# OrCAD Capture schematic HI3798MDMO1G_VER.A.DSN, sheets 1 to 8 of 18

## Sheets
1 SHEET_18: size A3
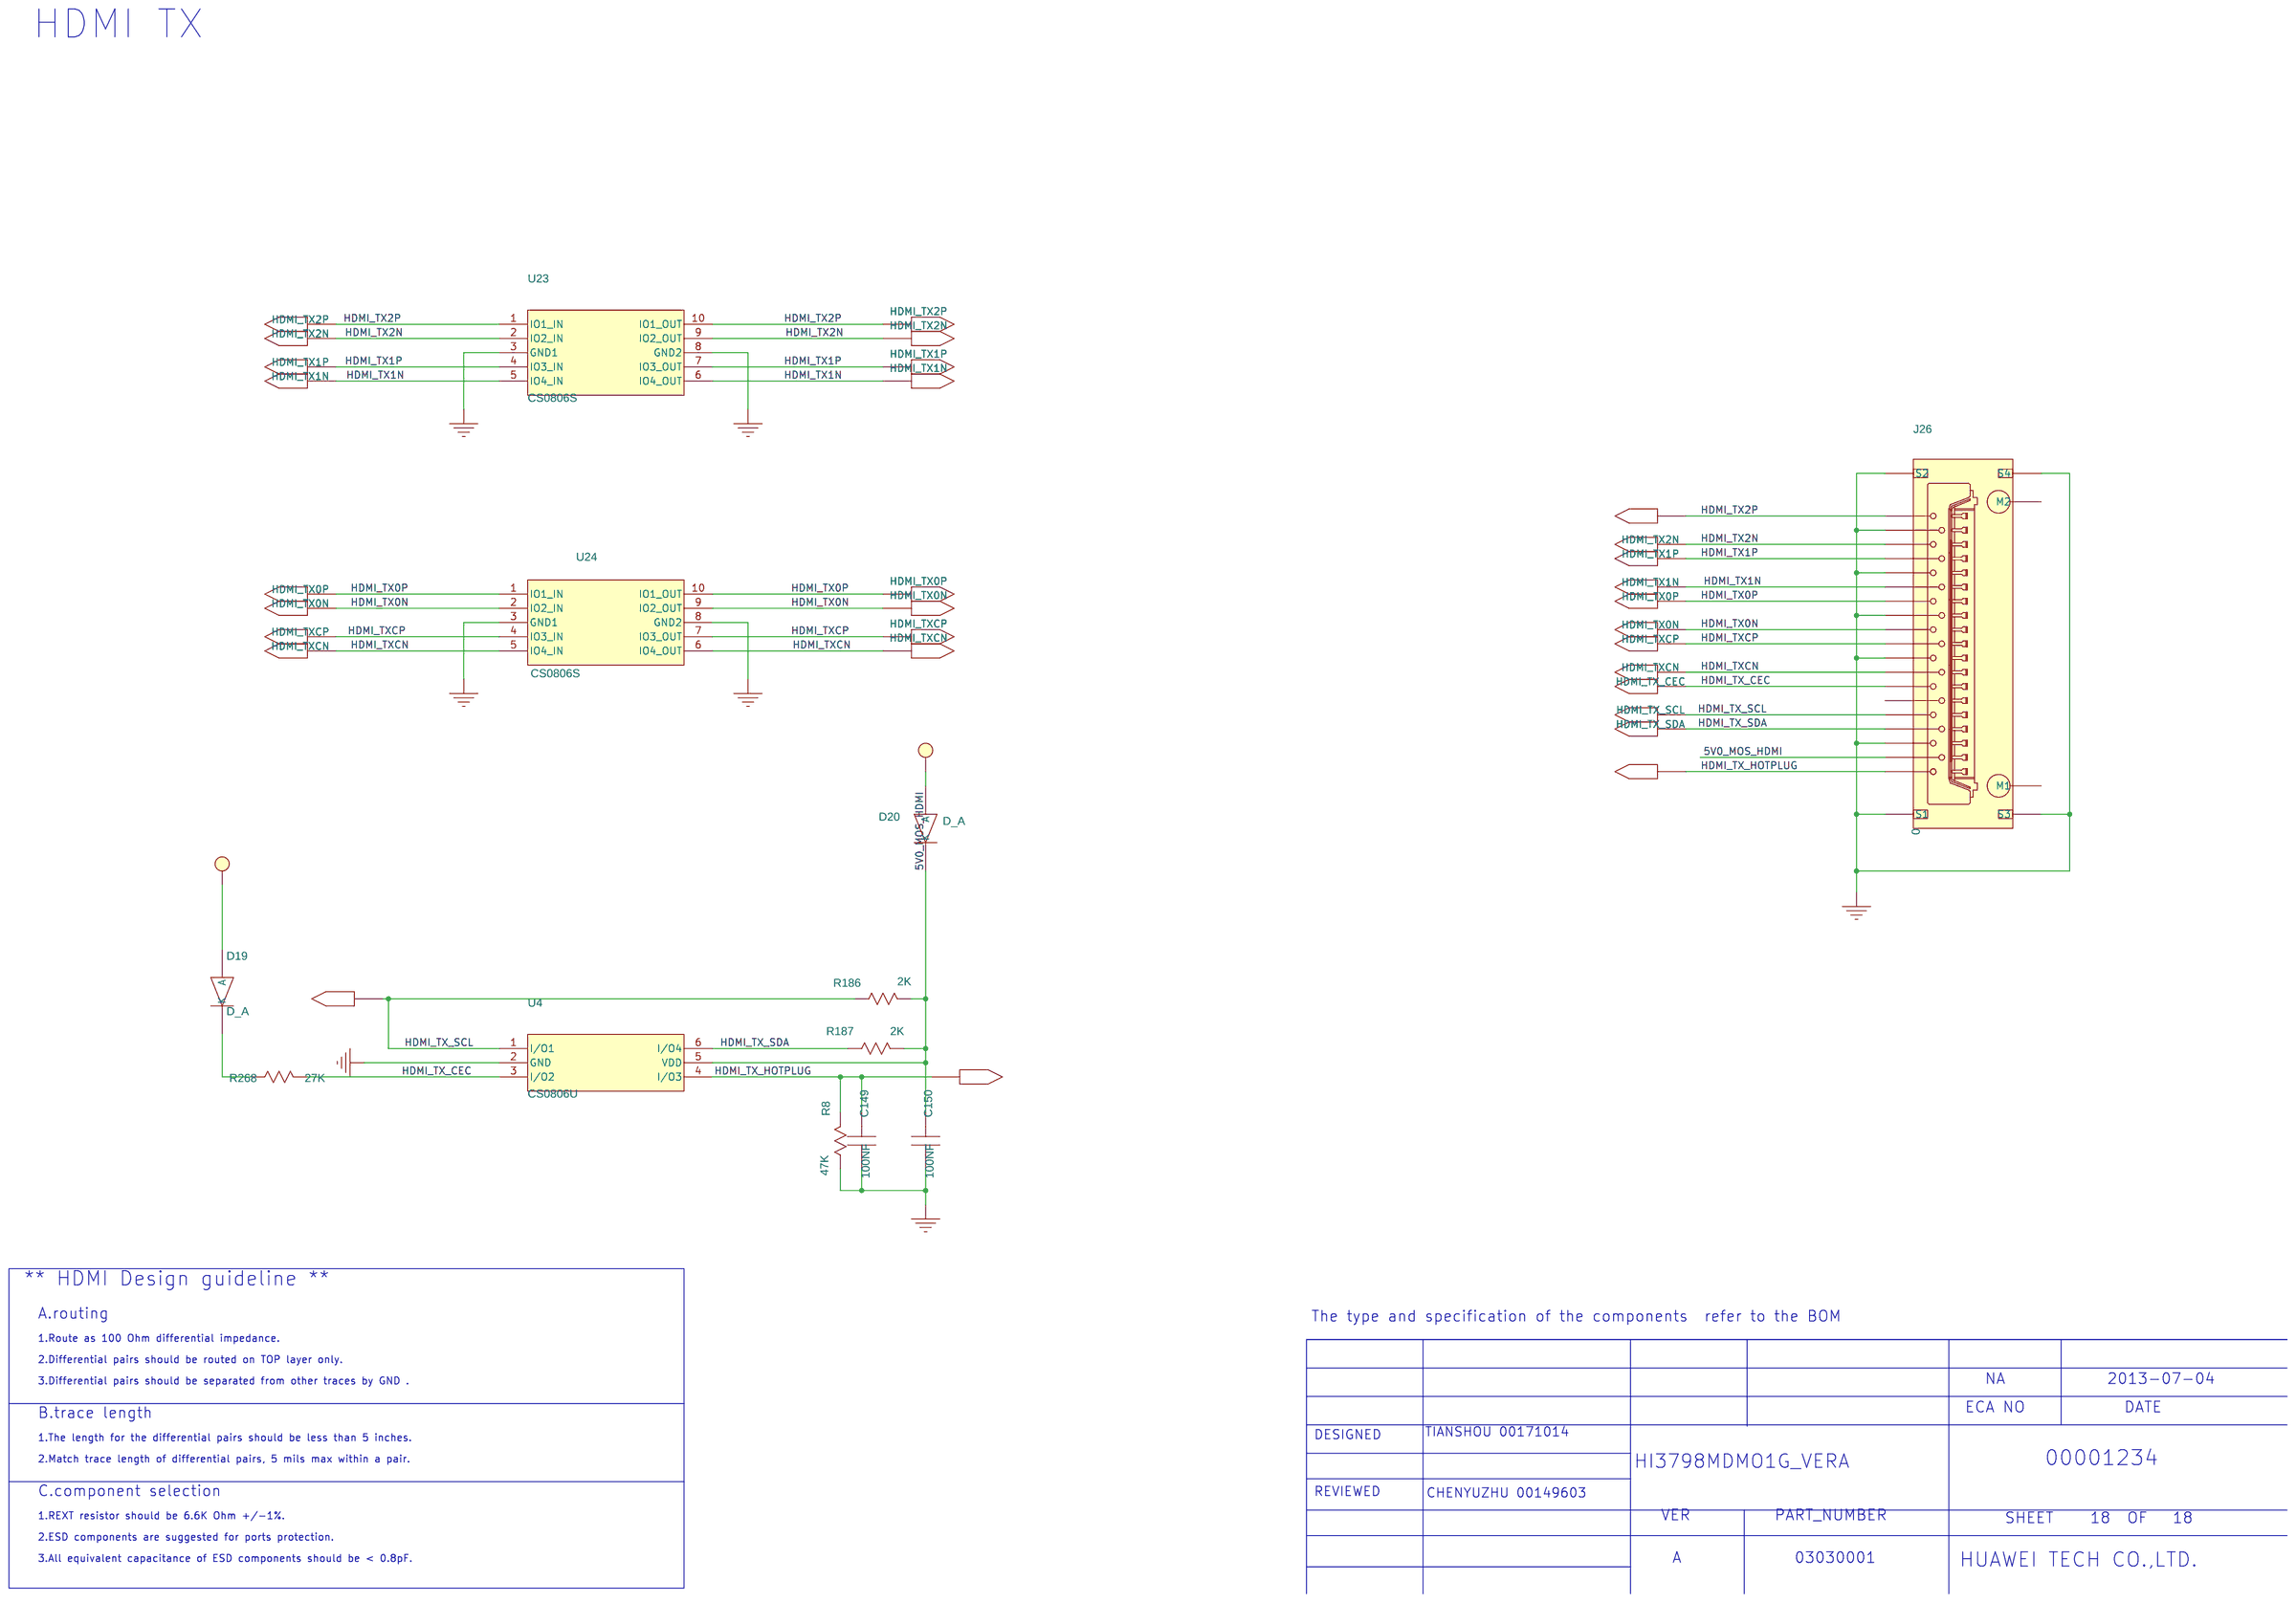
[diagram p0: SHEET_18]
2 SHEET_17: size A3
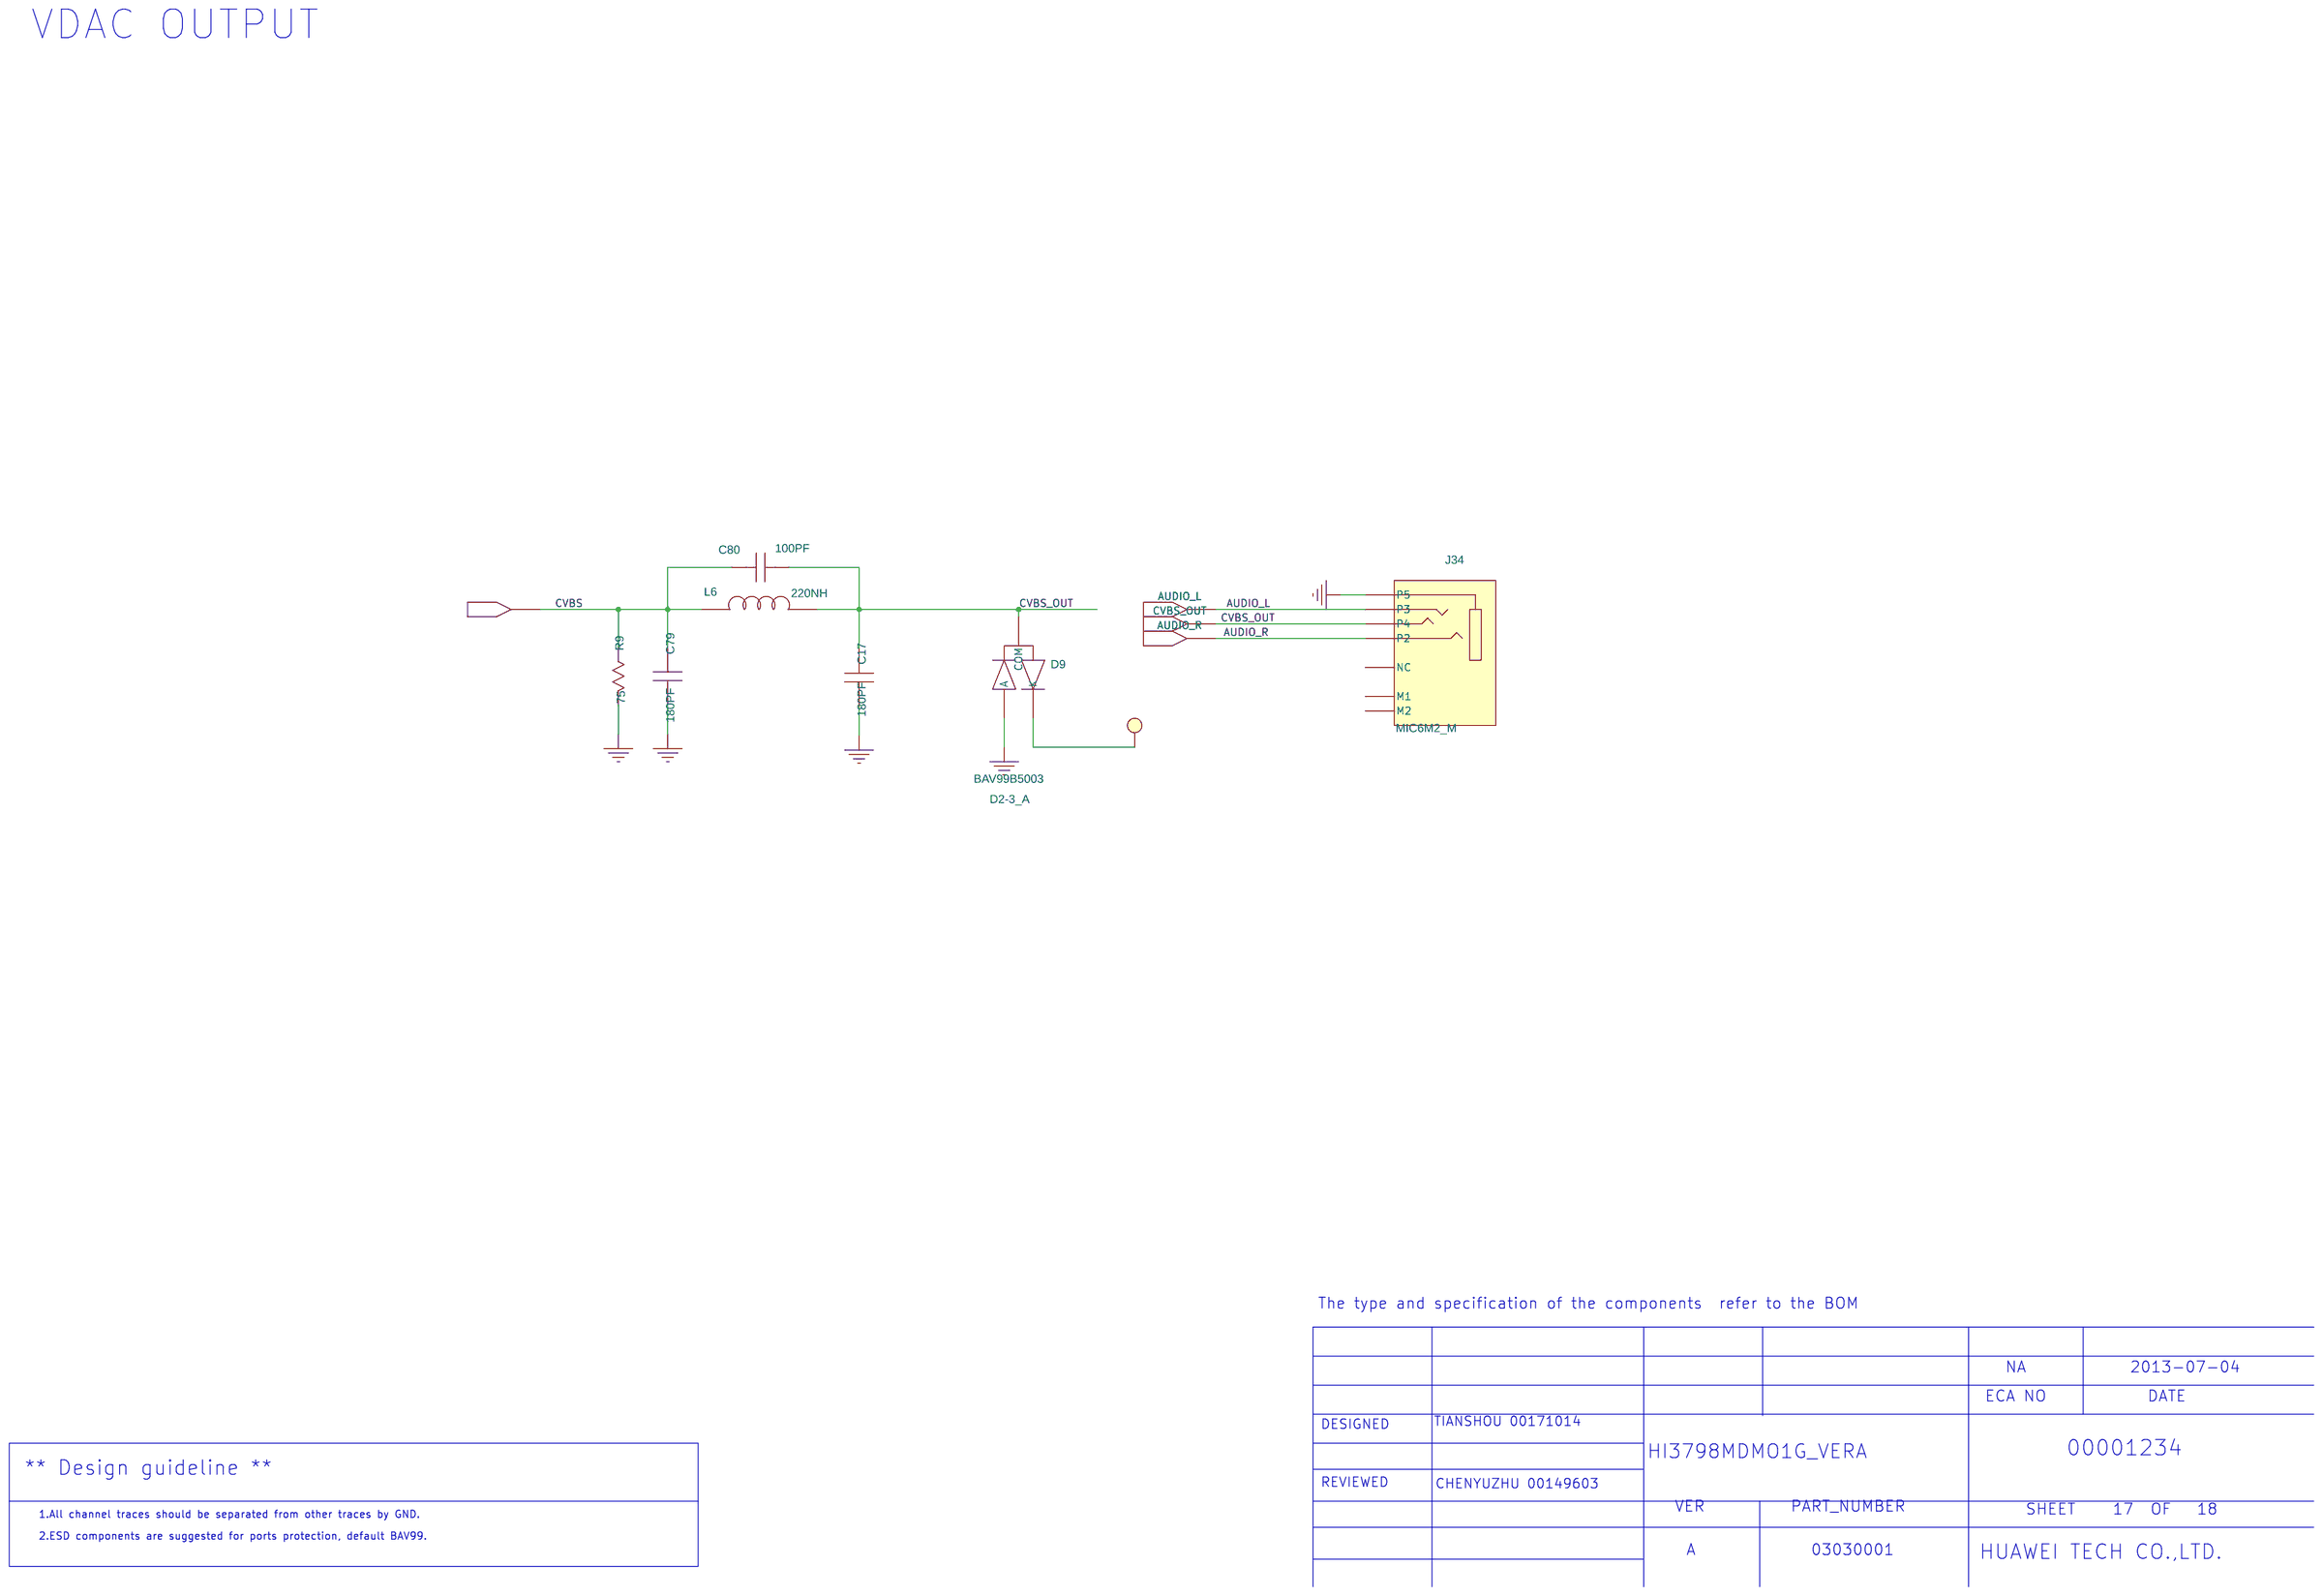
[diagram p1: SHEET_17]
3 SHEET_16: size A3
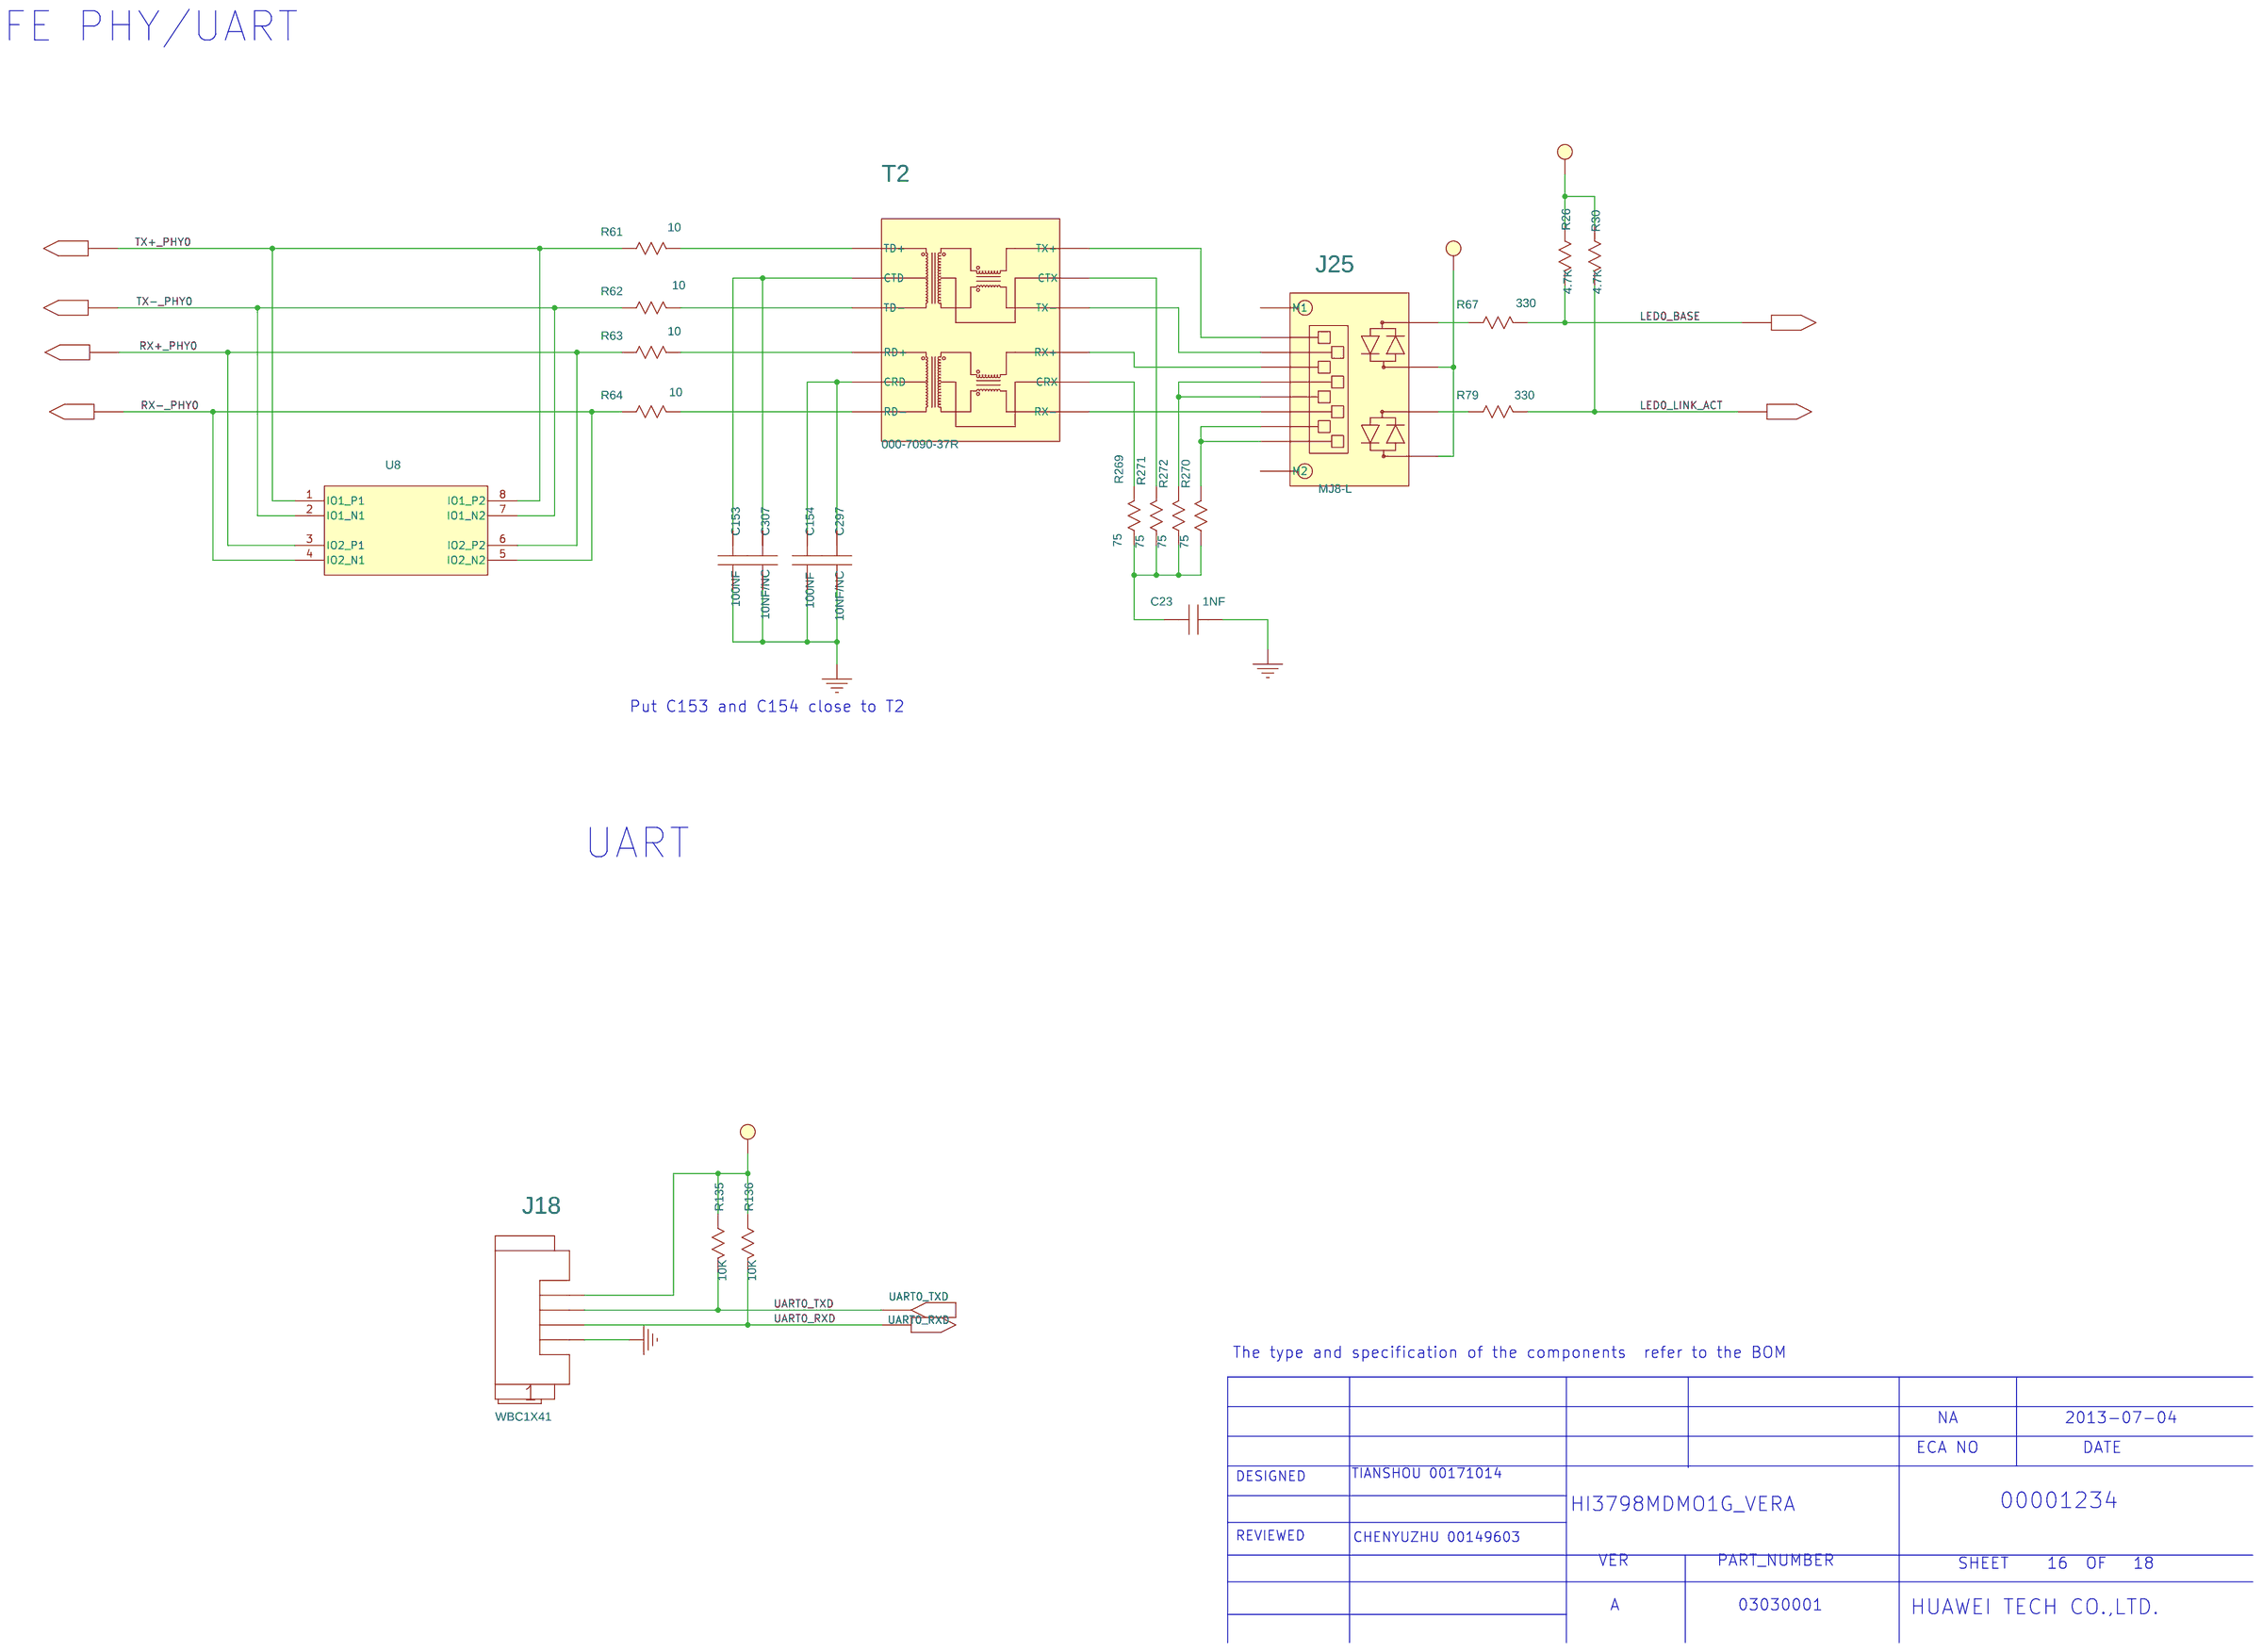
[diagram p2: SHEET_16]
4 SHEET_15: size A3
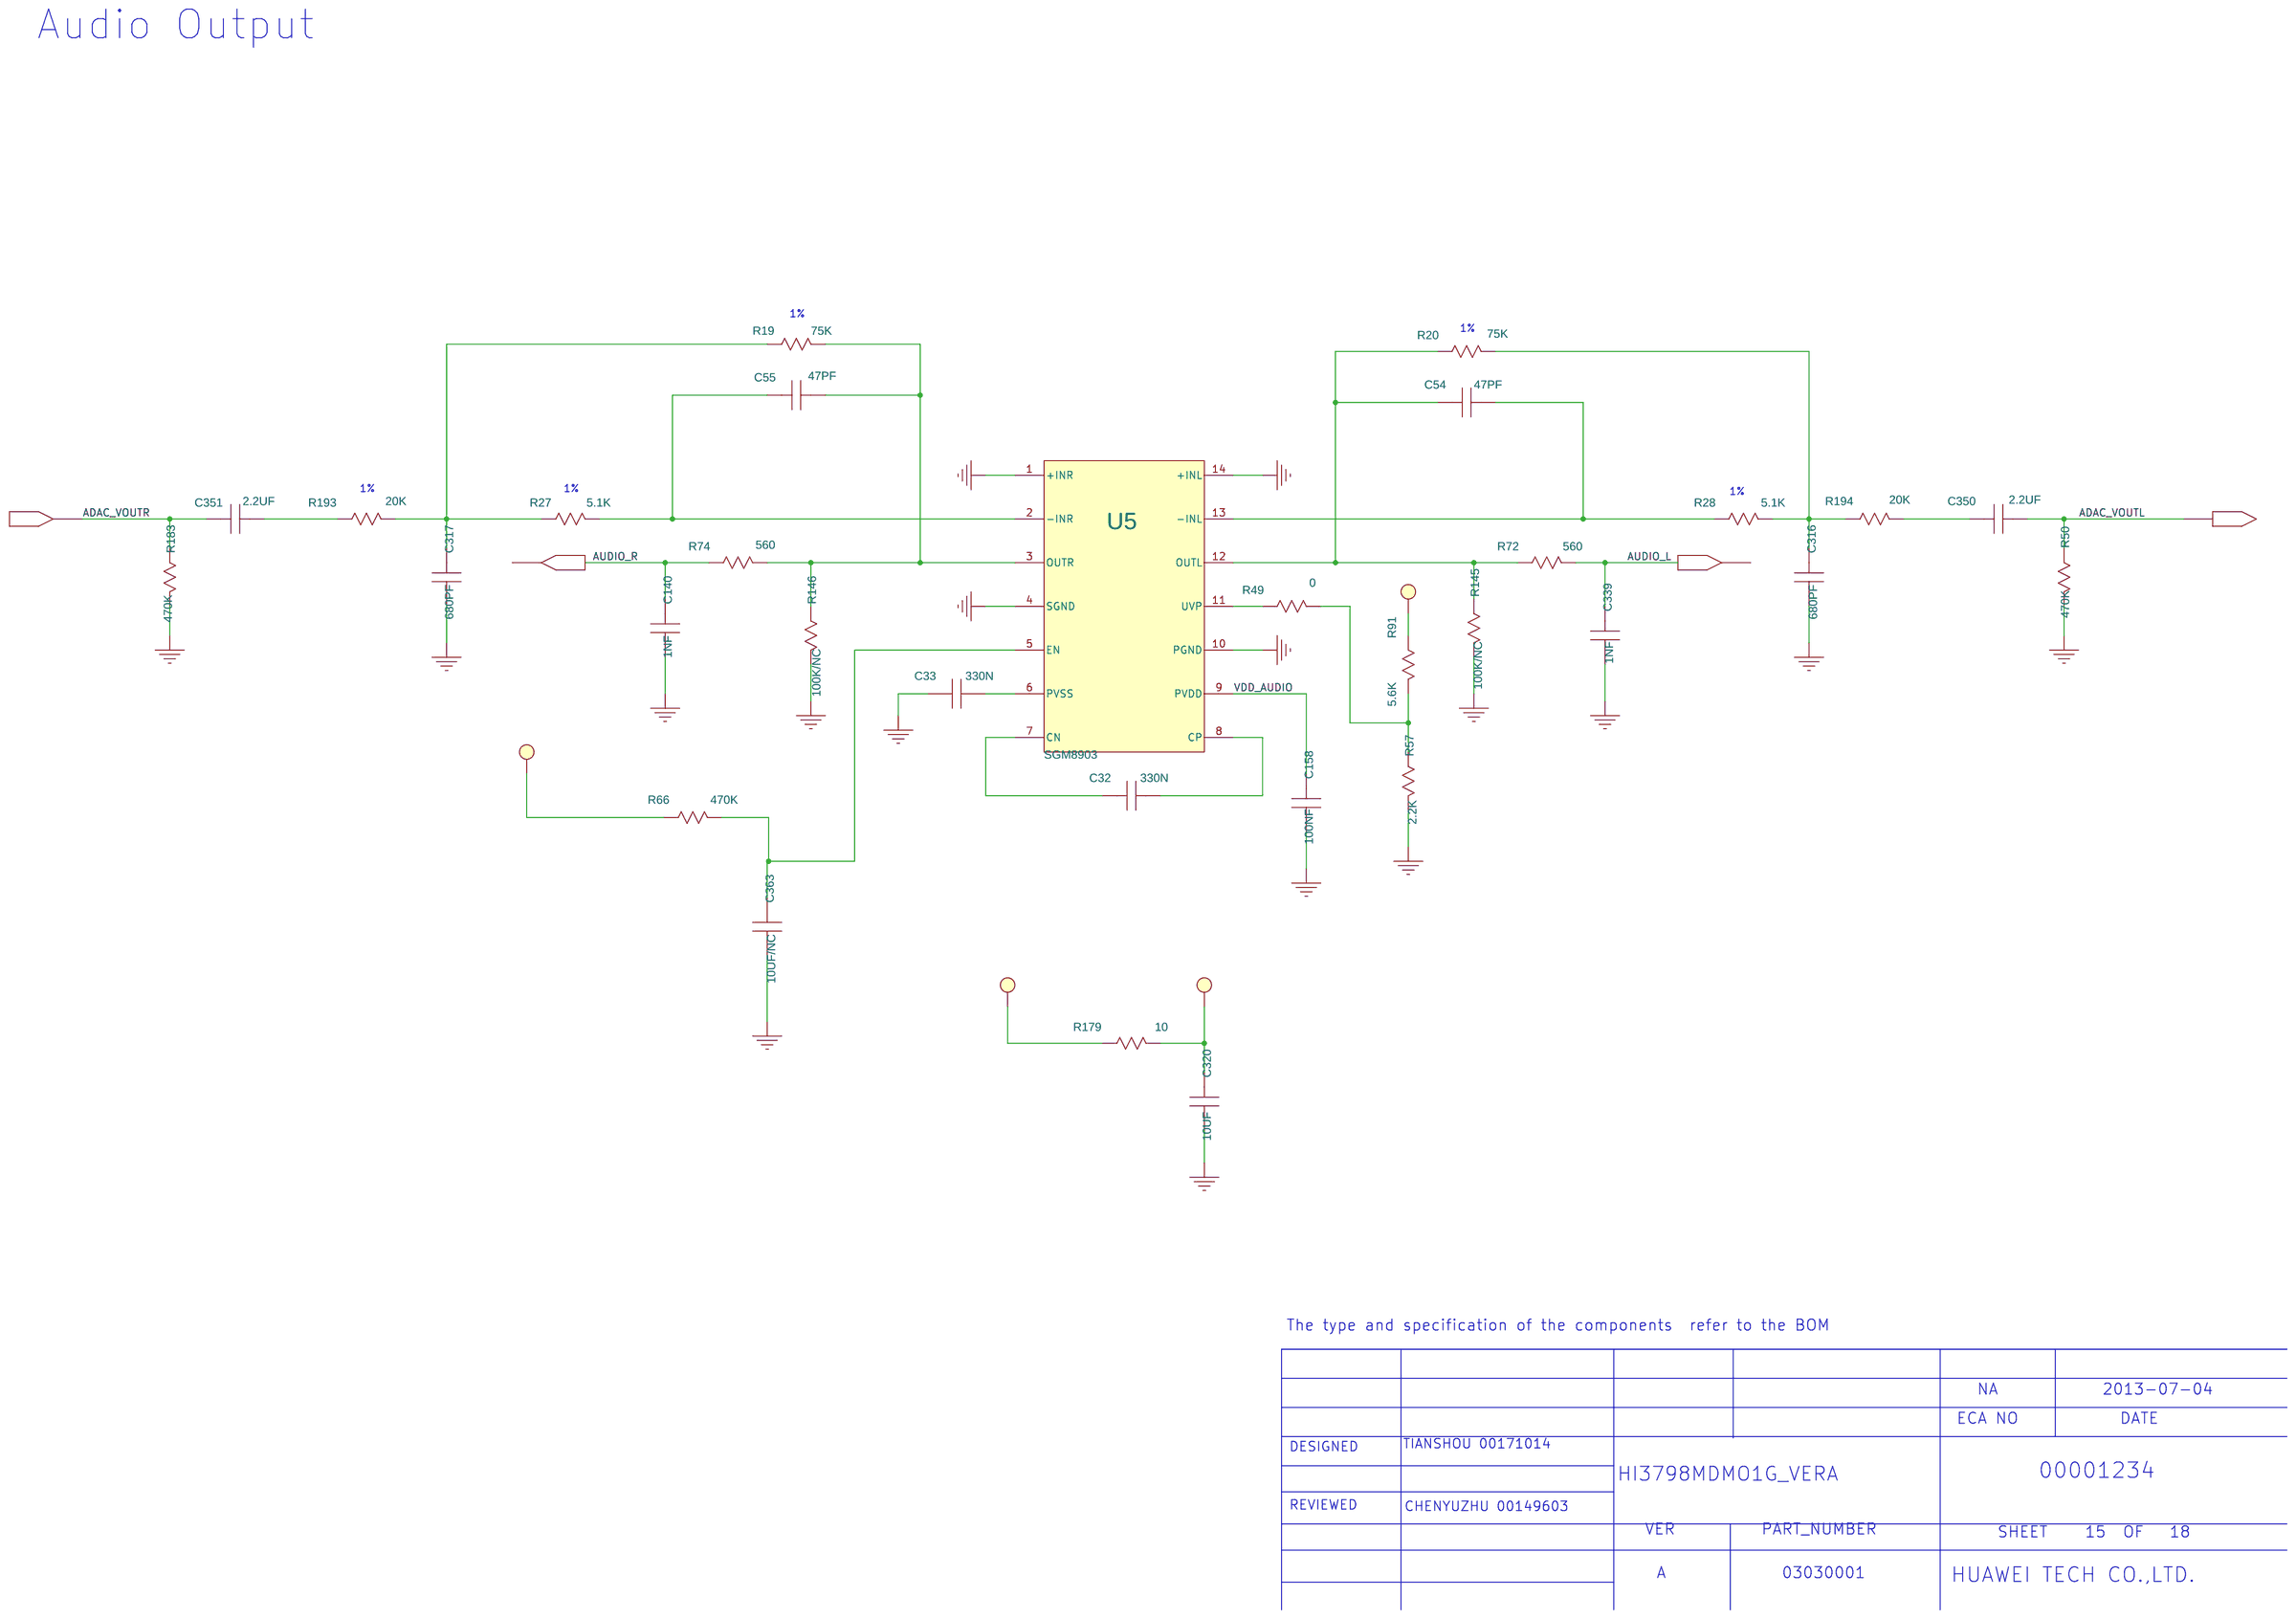
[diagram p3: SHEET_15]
5 SHEET_14: size A3
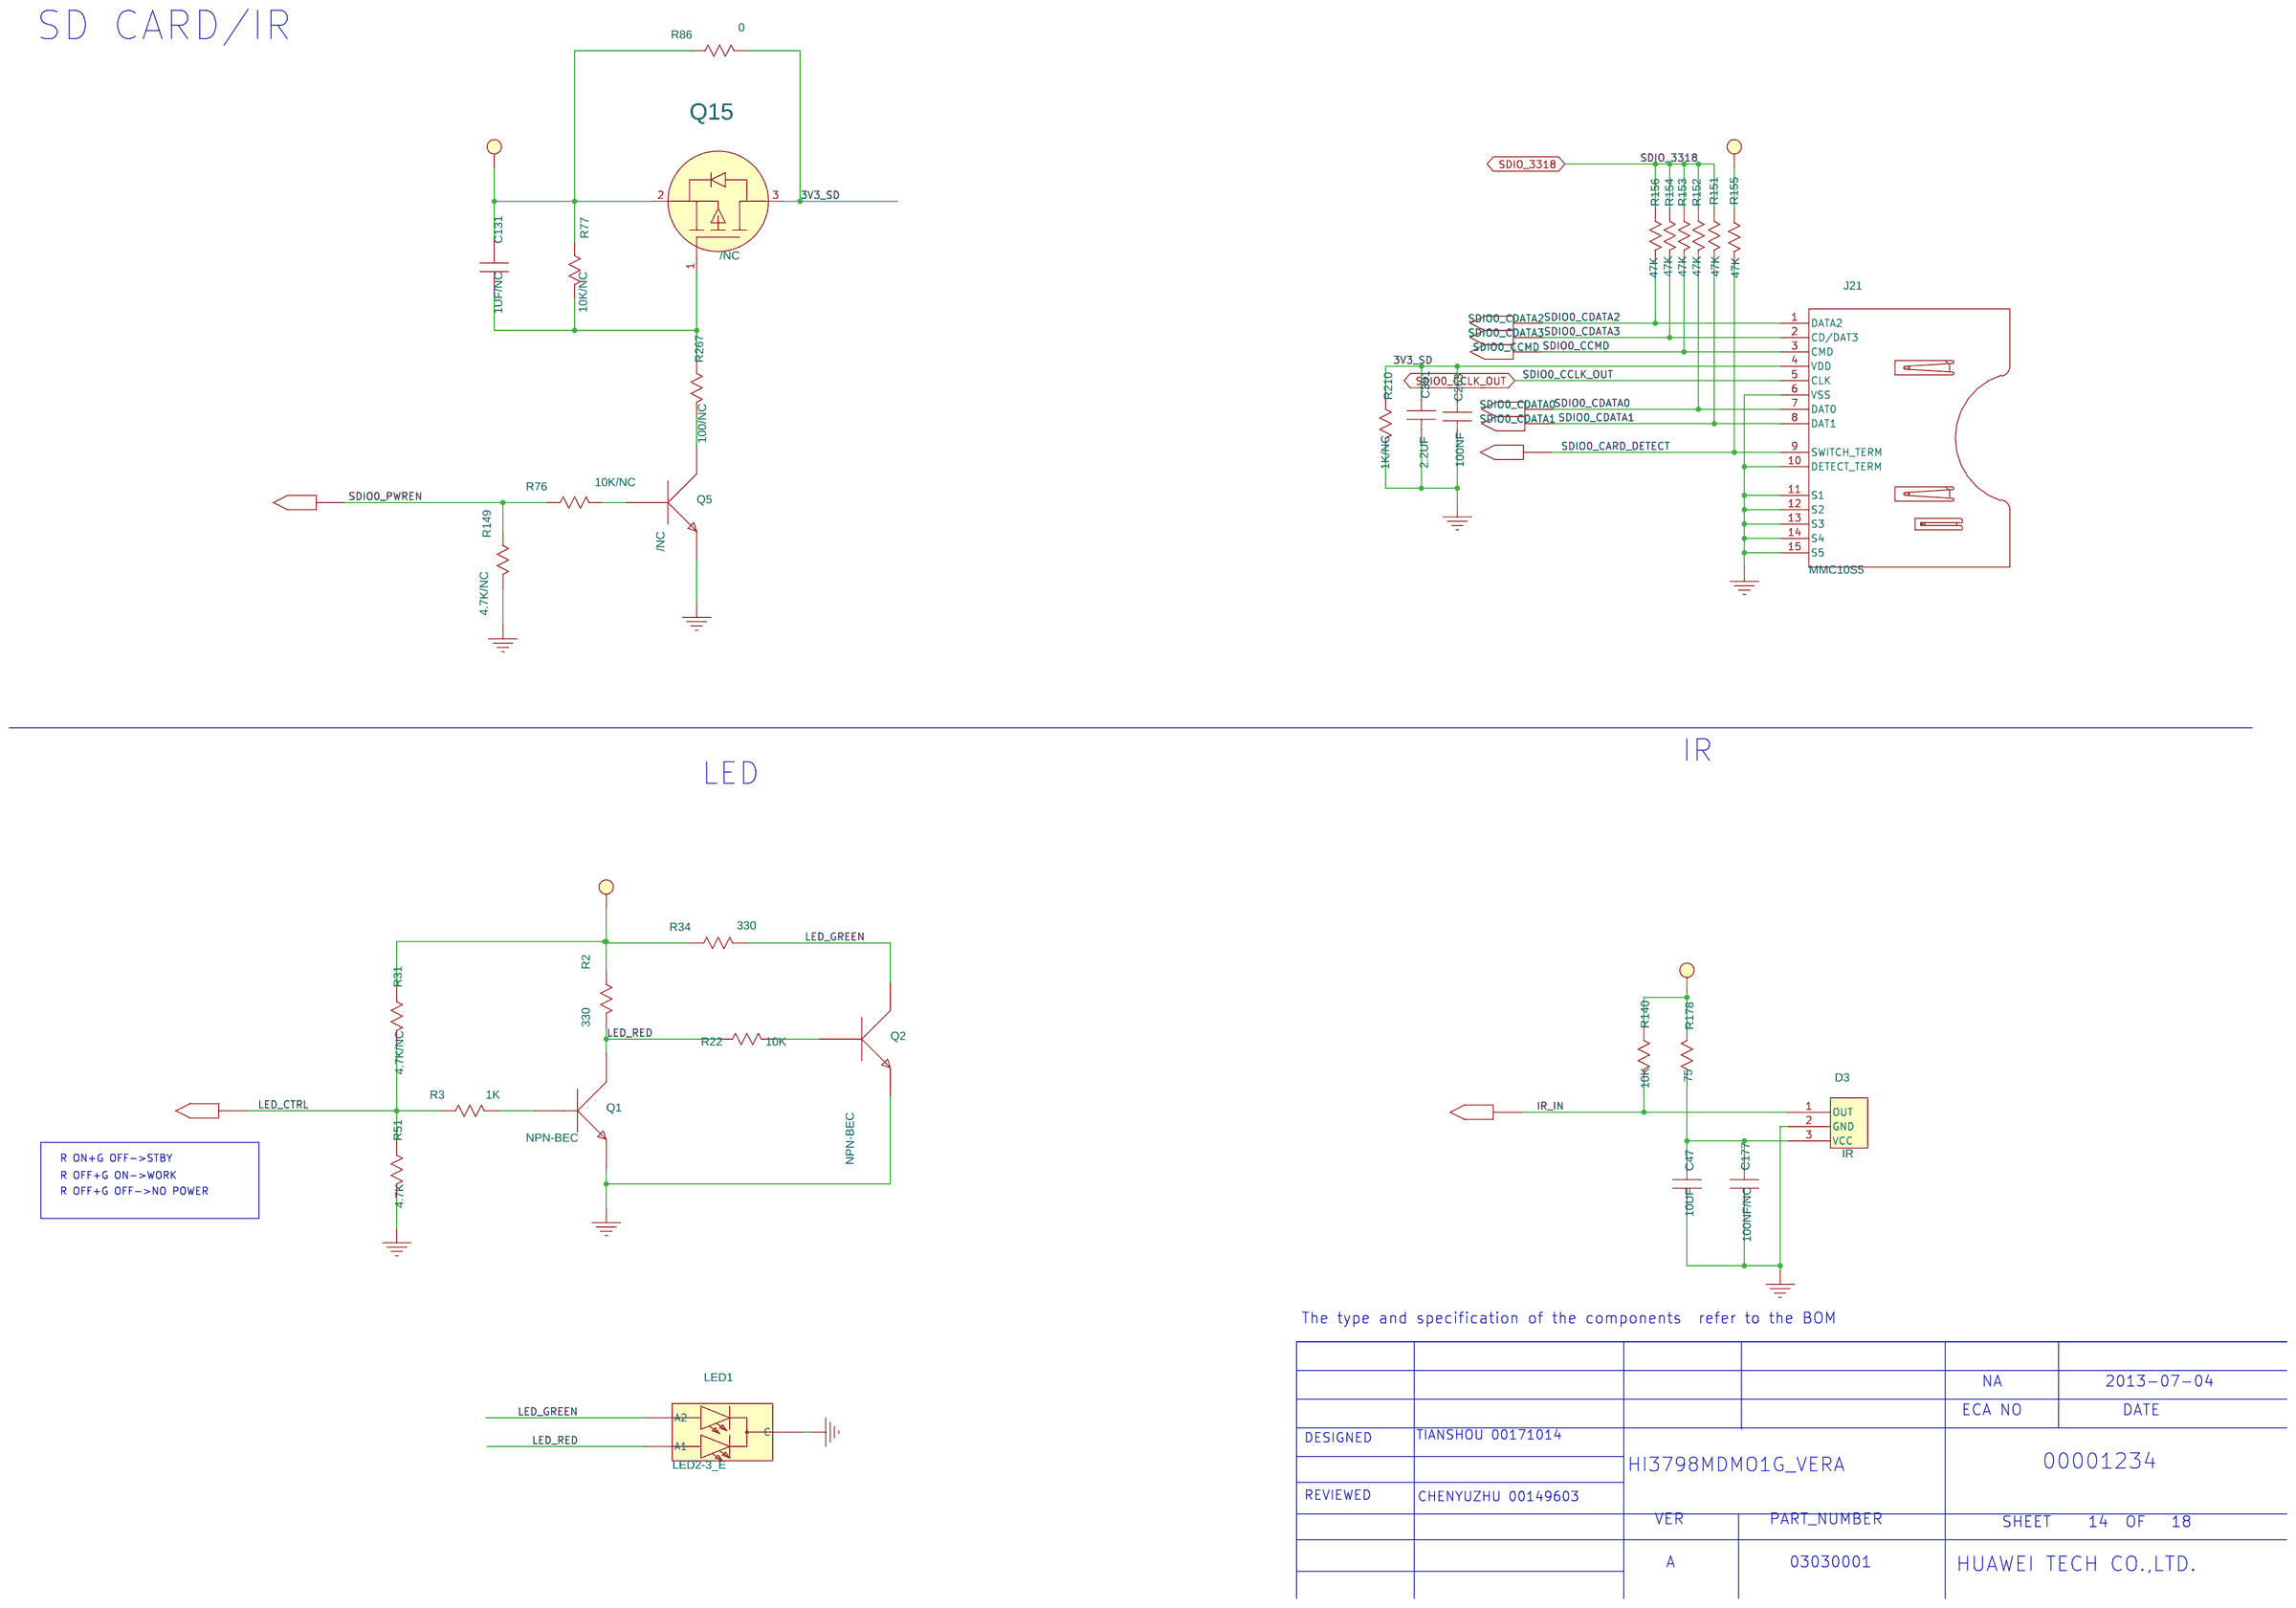
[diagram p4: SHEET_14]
6 SHEET_13: size A3
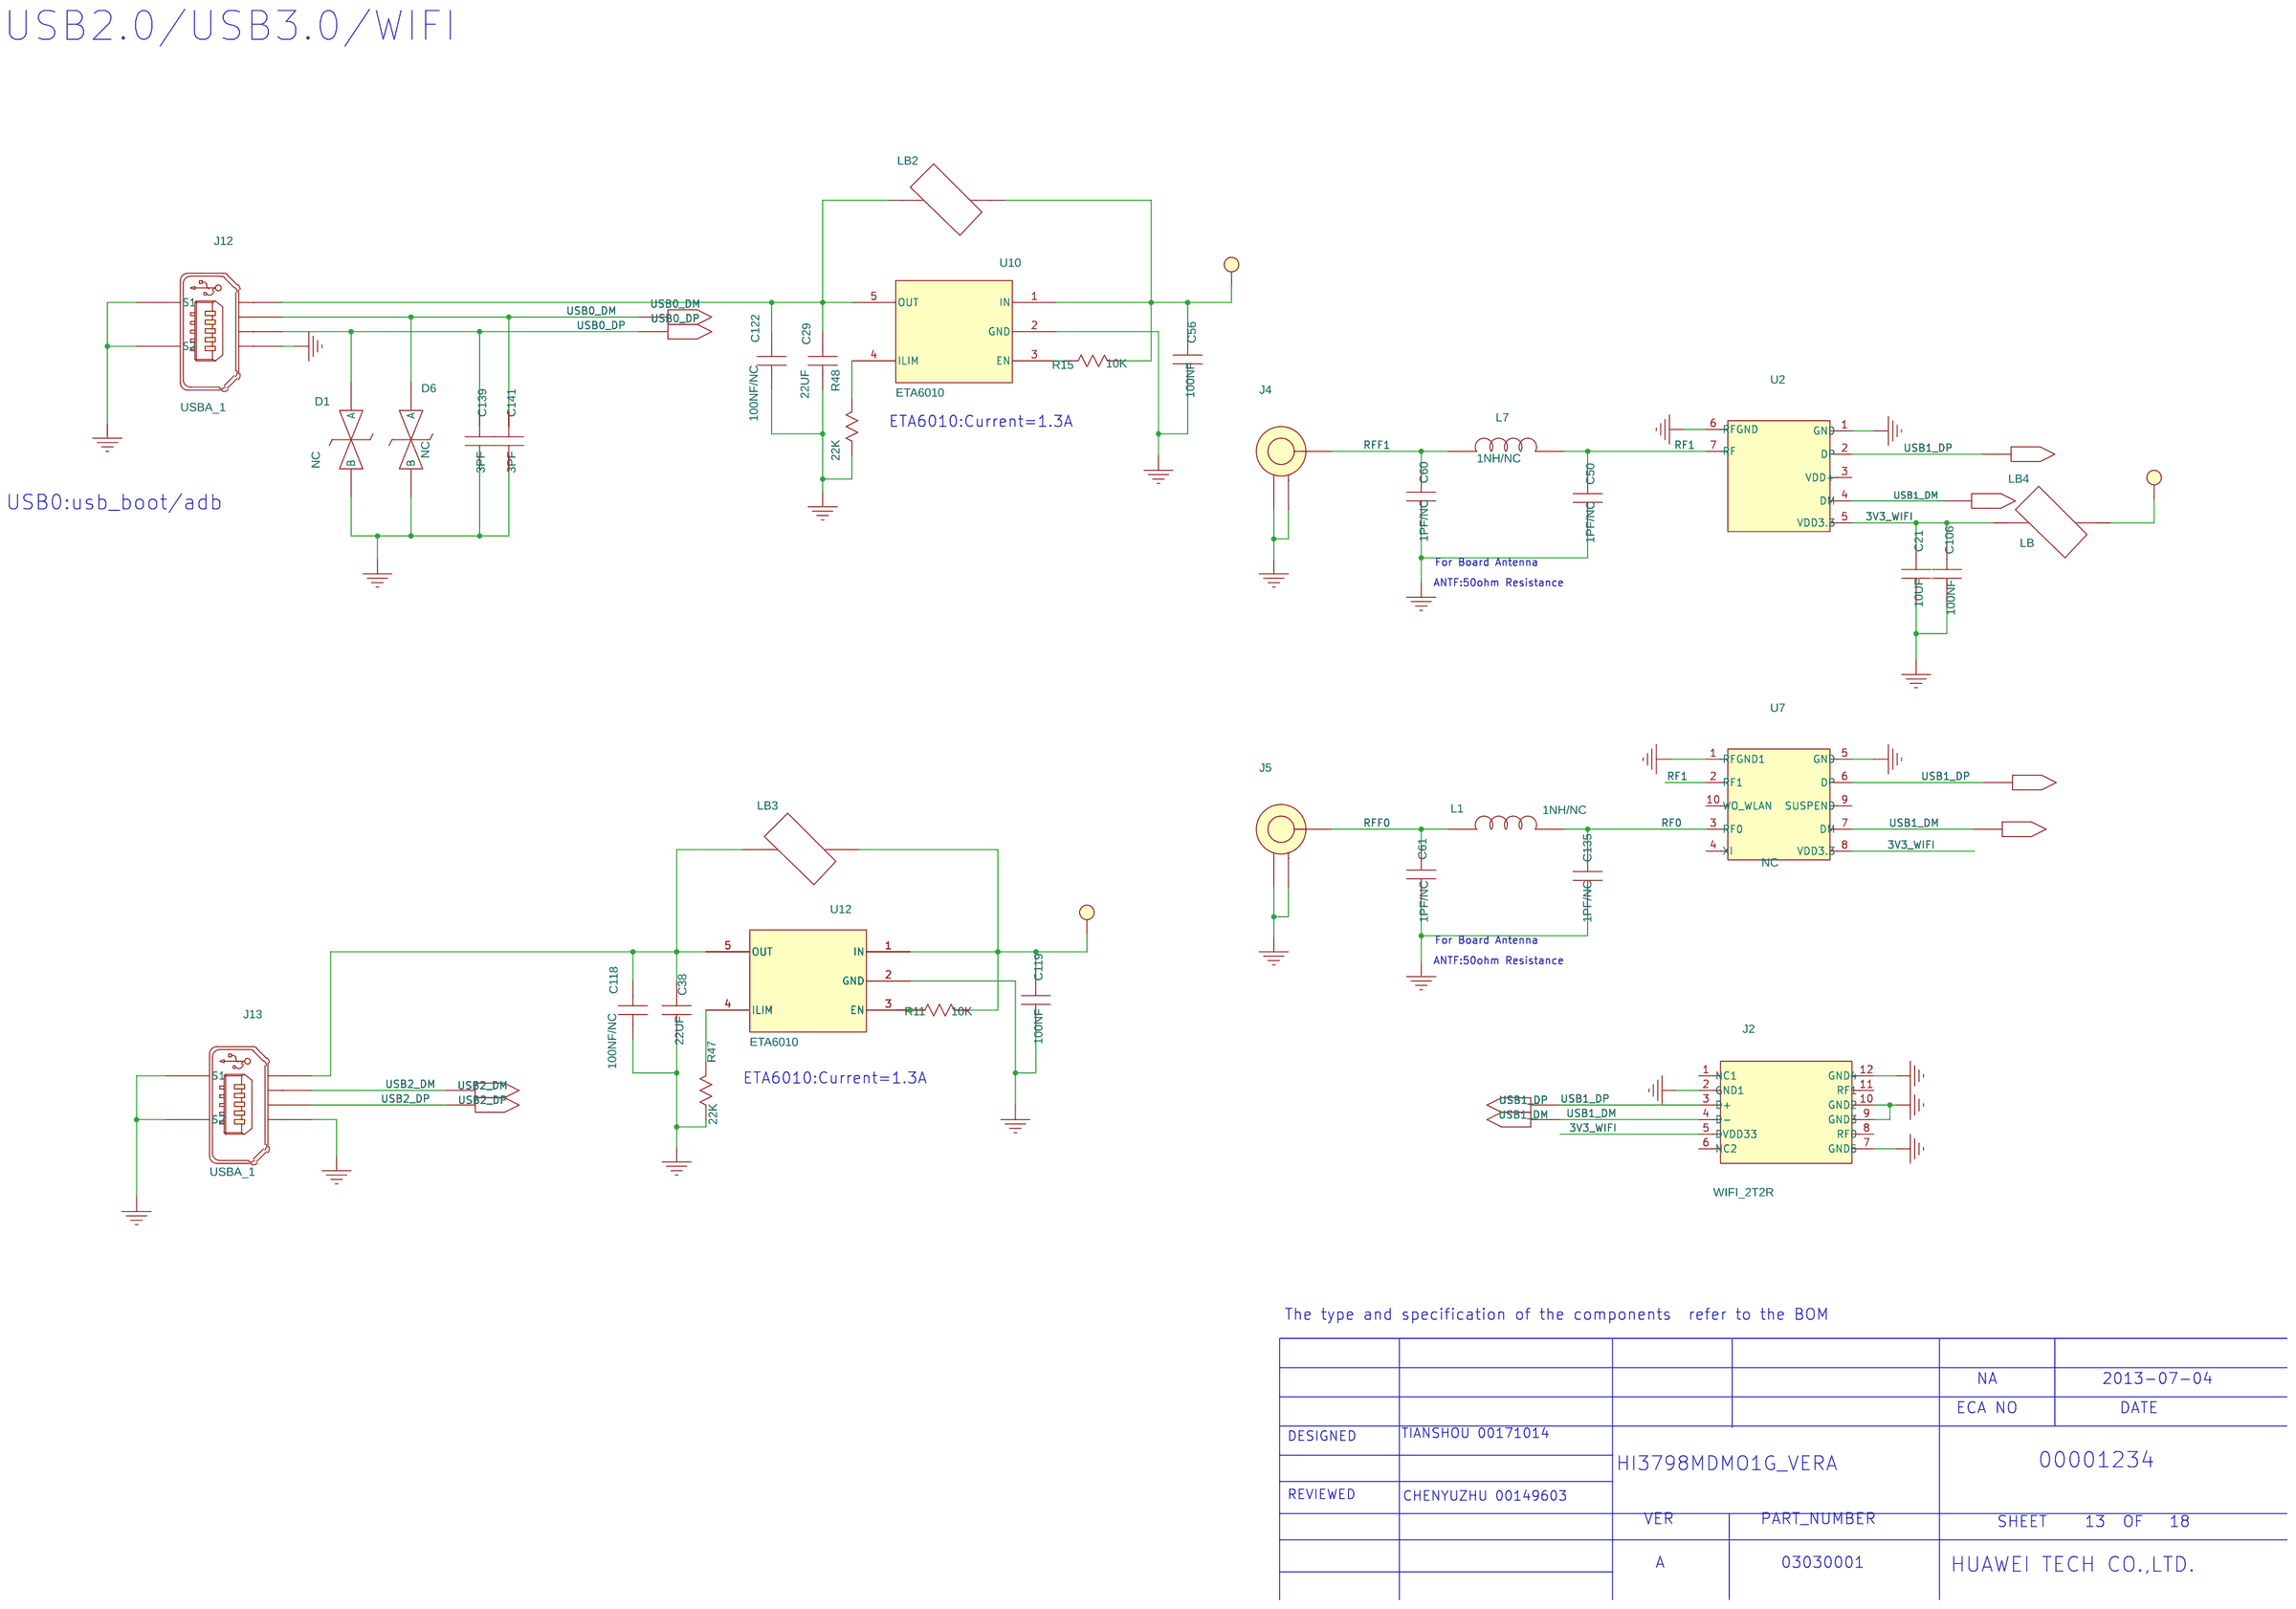
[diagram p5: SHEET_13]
7 SHEET_12: size A3
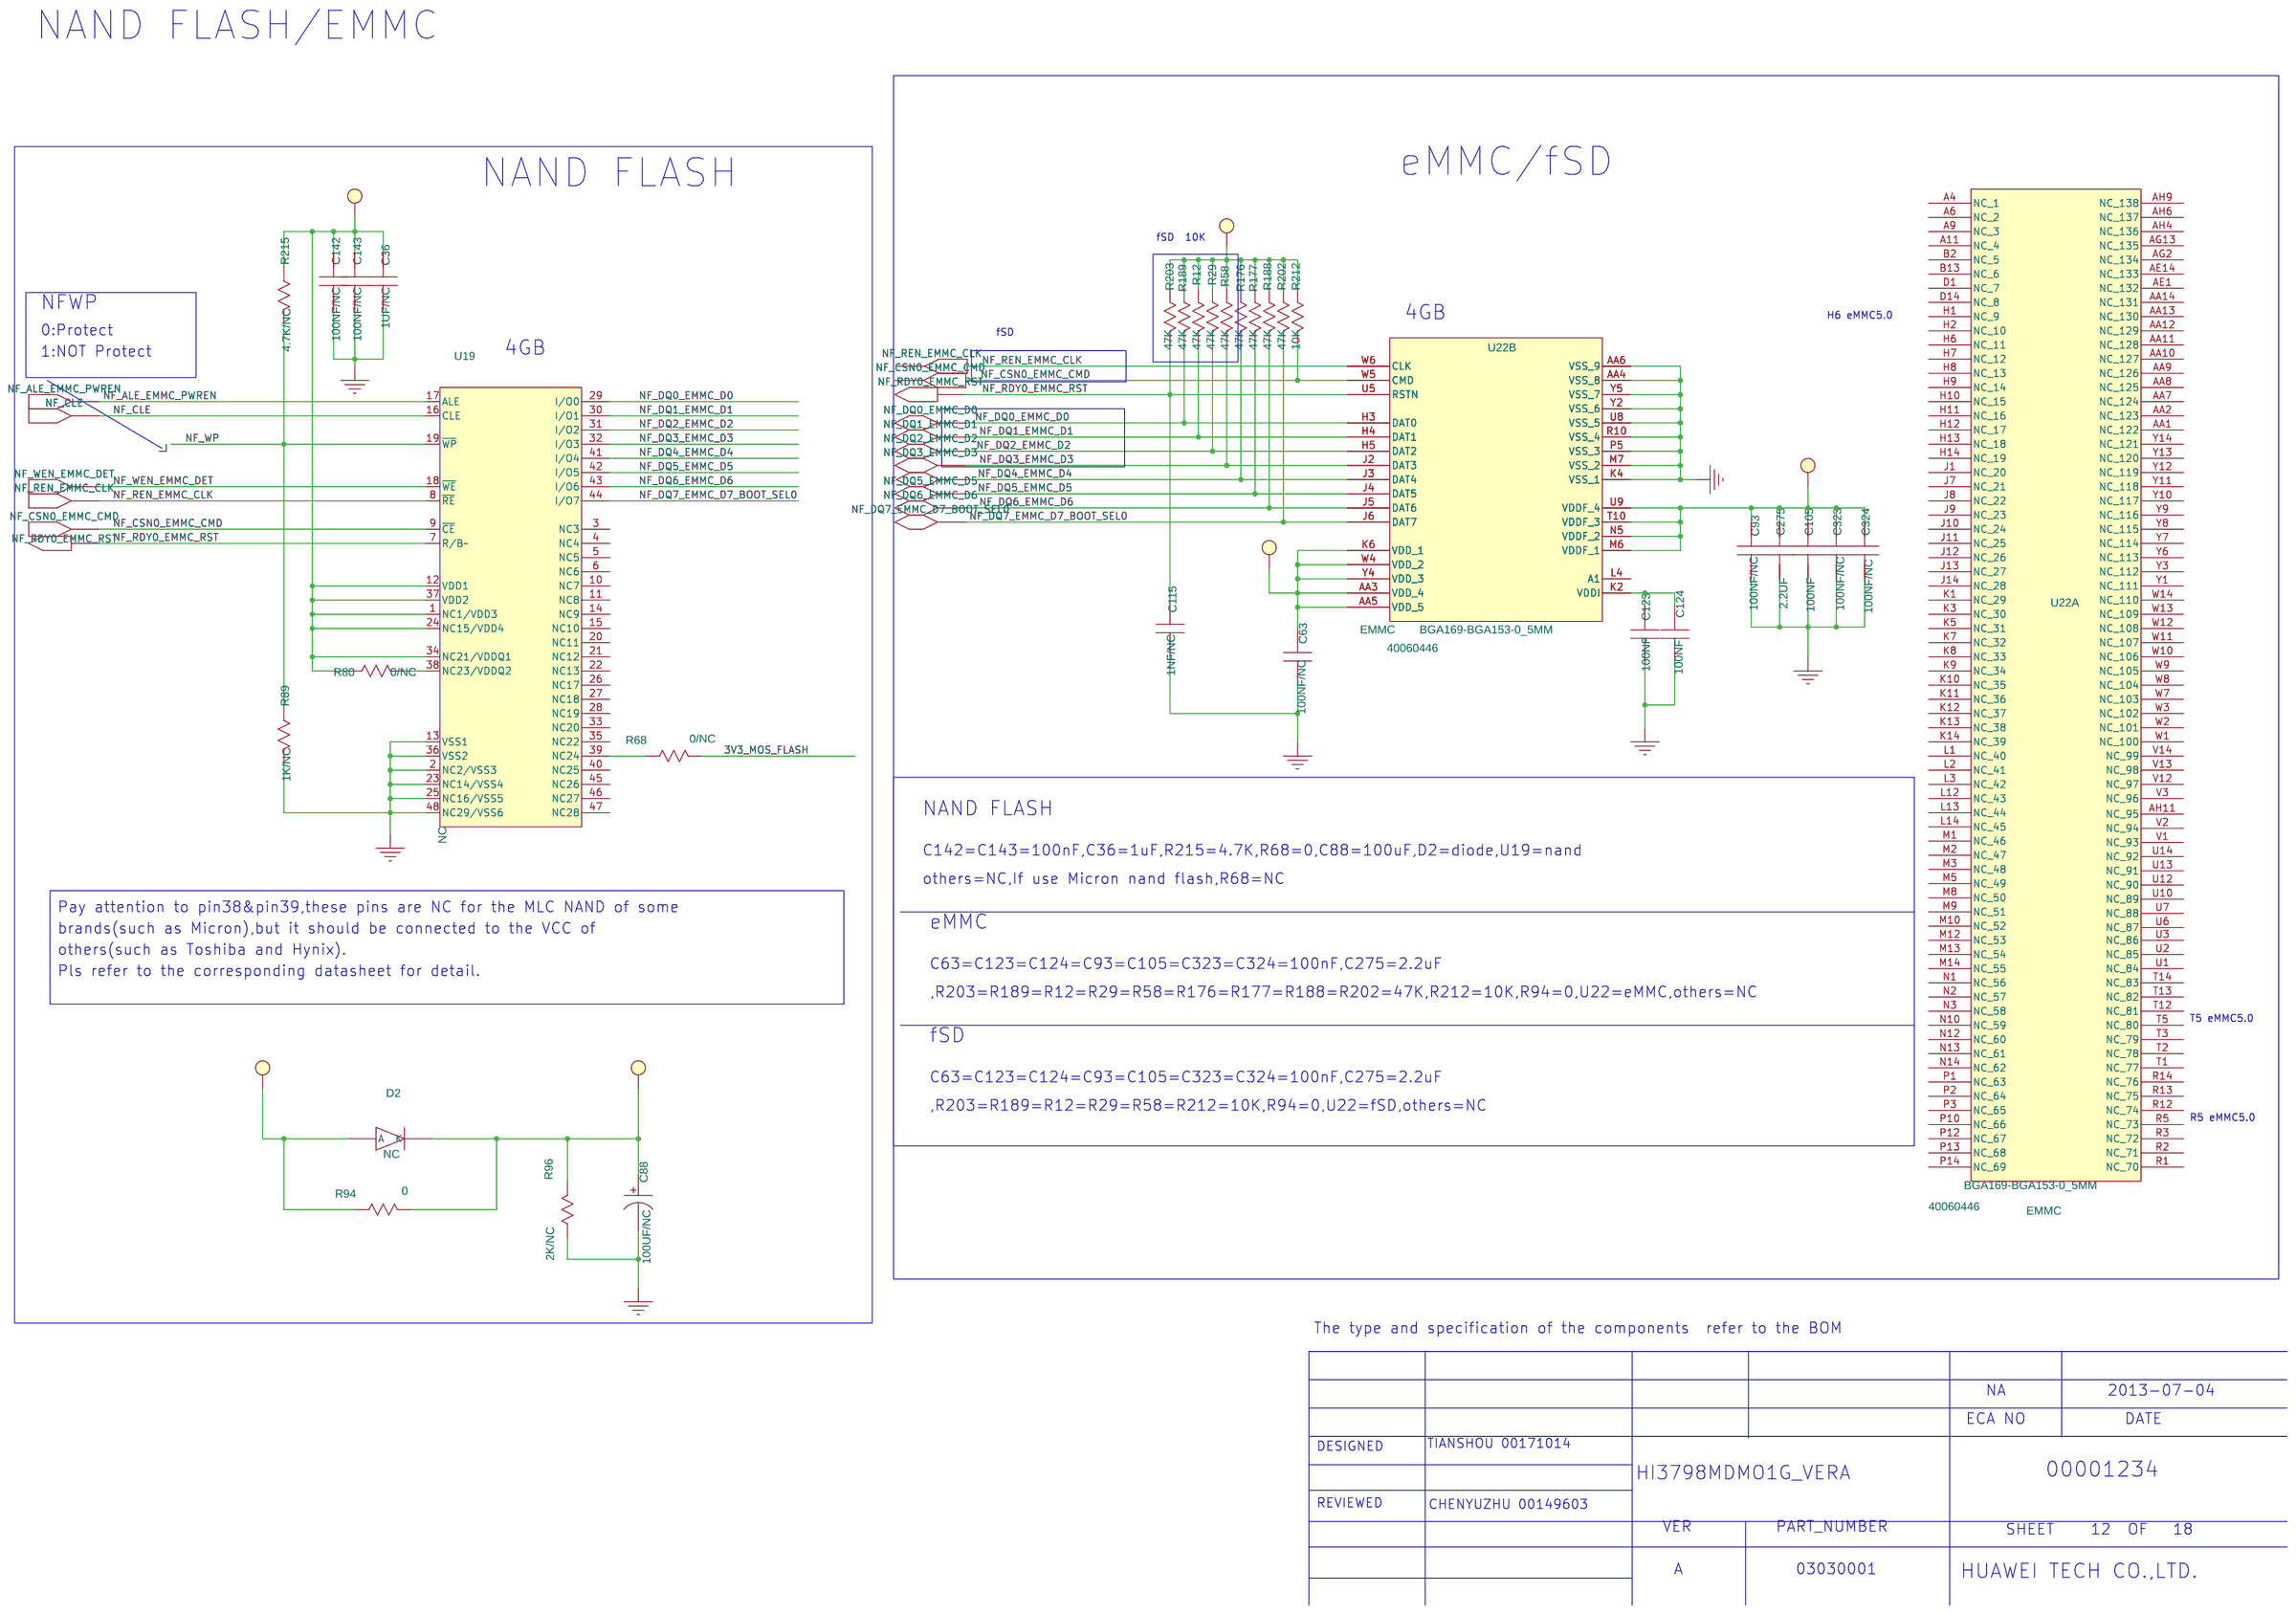
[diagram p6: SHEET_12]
8 SHEET_11: size A3
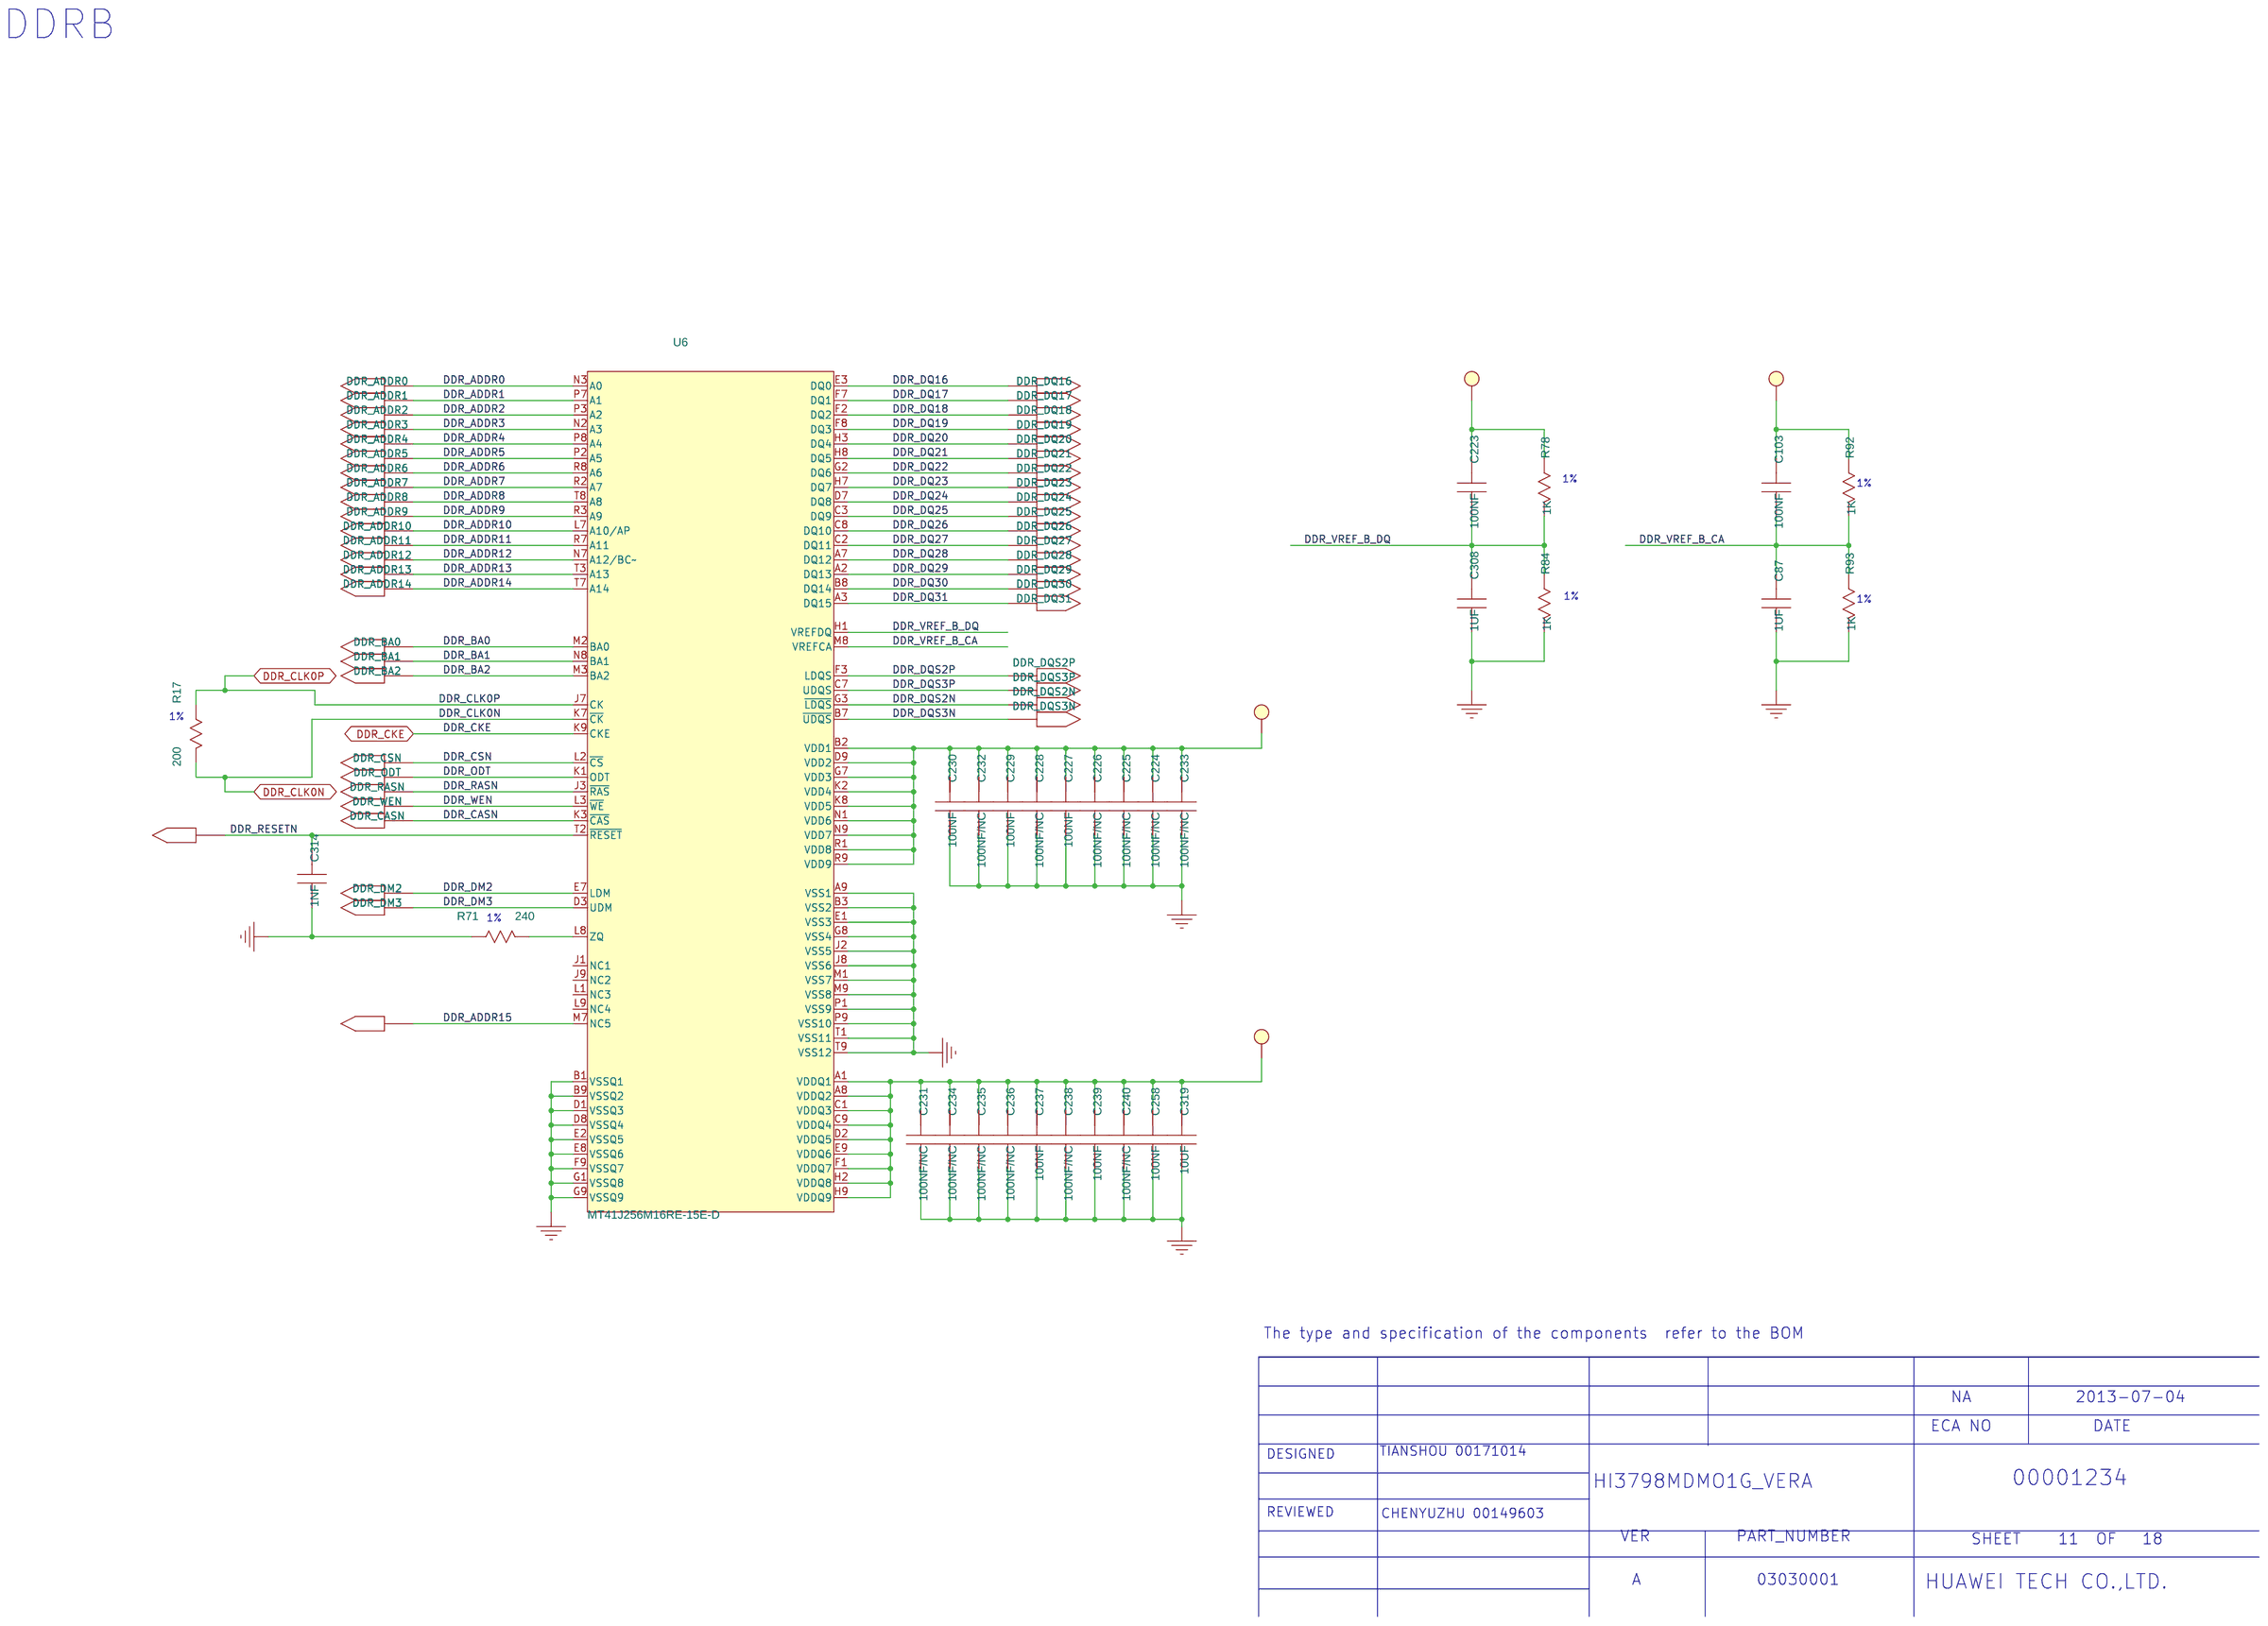
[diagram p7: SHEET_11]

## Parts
sheet SHEET_11
C87  1UF  [SC0402]
C103  100NF  [SC0402]
C223  100NF  [SC0402]
C224  100NF/NC  [SC0402]
C225  100NF/NC  [SC0402]
C226  100NF/NC  [SC0402]
C227  100NF  [SC0402]
C228  100NF/NC  [SC0402]
C229  100NF  [SC0402]
C230  100NF  [SC0402]
C231  100NF/NC  [SC0402]
C232  100NF/NC  [SC0402]
C233  100NF/NC  [SC0402]
C234  100NF/NC  [SC0402]
C235  100NF/NC  [SC0402]
C236  100NF/NC  [SC0402]
C237  100NF  [SC0402]
C238  100NF/NC  [SC0402]
C239  100NF  [SC0402]
C240  100NF/NC  [SC0402]
C258  100NF  [SC0402]
C308  1UF  [SC0402]
C314  1NF  [SC0402]
C319  10UF  [SC0805]
R17  200  [SR0402]
R71  240  [SR0402]
R78  1K  [SR0402]
R84  1K  [SR0402]
R92  1K  [SR0402]
R93  1K  [SR0402]
U6  MT41J256M16RE-15E-D  [BGA96-32-1609I]
sheet SHEET_12
C36  1UF/NC  [SC0603]
C63  100NF/NC  [SC0402]
C88  100UF/NC  [SAC6666]
C93  100NF/NC  [SC0402]
C105  100NF  [SC0402]
C115  1NF/NC  [SC0402]
C123  100NF  [SC0402]
C124  100NF  [SC0402]
C142  100NF/NC  [SC0402]
C143  100NF/NC  [SC0402]
C275  2.2UF  [SC0603]
C323  100NF/NC  [SC0402]
C324  100NF/NC  [SC0402]
D2  NC  [HSOD323A]
R12  47K  [SR0402]
R29  47K  [SR0402]
R58  47K  [SR0402]
R68  0/NC  [SR0402]
R80  0/NC  [SR0402]
R89  1K/NC  [SR0402]
R94  0  [SR0805]
R96  2K/NC  [SR0402]
R176  47K  [SR0402]
R177  47K  [SR0402]
R188  47K  [SR0402]
R189  47K  [SR0402]
R202  47K  [SR0402]
R203  47K  [SR0402]
R212  10K  [SR0402]
R215  4.7K/NC  [SR0402]
U19  NC  [SOP48-20-720B]
U22  EMMC  [BGA169-BGA153-0_5MM]  (sections A,B)
sheet SHEET_13
C21  10UF  [SC0603]
C29  22UF  [SC0805]
C38  22UF  [SC0805]
C50  1PF/NC  [SC0402]
C56  100NF  [SC0603]
C60  1PF/NC  [SC0402]
C61  1PF/NC  [SC0402]
C106  100NF  [SC0603]
C118  100NF/NC  [SC0603]
C119  100NF  [SC0603]
C122  100NF/NC  [SC0603]
C135  1PF/NC  [SC0402]
C139  3PF  [SC0402]
C141  3PF  [SC0402]
D1  NC  [SC0402]
D6  NC  [SC0402]
J2  WIFI_2T2R  [SIP12-2_0MM-1827]
J4  NC  [HSCOX-AMC-TM-A]
J5  NC  [HSCOX-AMC-TM-A]
J12  USBA_1  [USB4-1415]
J13  USBA_1  [USB4-1415]
L1  1NH/NC  [SL0402]
L7  1NH/NC  [SL0402]
LB2  NC  [SL0603]
LB3  NC  [SL0603]
LB4  LB  [SL0805]
R11  10K  [SR0402]
R15  10K  [SR0402]
R47  22K  [SR0402]
R48  22K  [SR0402]
U2  NC  [CDTWIFI]
U7  NC  [CDTWIFI10]
U10  ETA6010  [SOT23-5]
U12  ETA6010  [SOT23-5]
sheet SHEET_14
C47  10UF  [SC0603]
C131  1UF/NC  [SC0402]
C177  100NF/NC  [SC0402]
C263  100NF  [SC0603]
C391  2.2UF  [SC0603]
D3  IR  [SEN3-100C]
J21  MMC10S5  [MICRO_SD8-PUSH]
LED1  LED2-3_E  [LED3C-100C]
Q1  NPN-BEC  [SOT23]
Q2  NPN-BEC  [SOT23]
Q5  /NC  [SOT23]
Q15  /NC  [SOT23]
R2  330  [SR0402]
R3  1K  [SR0402]
R22  10K  [SR0402]
R31  4.7K/NC  [SR0402]
R34  330  [SR0402]
R51  4.7K  [SR0402]
R76  10K/NC  [SR0603]
R77  10K/NC  [SR0603]
R86  0  [SR0603]
R140  10K  [SR0402]
R149  4.7K/NC  [SR0603]
R151  47K  [SR0402]
R152  47K  [SR0402]
R153  47K  [SR0402]
R154  47K  [SR0402]
R155  47K  [SR0402]
R156  47K  [SR0402]
R178  75  [SR0402]
R210  1K/NC  [SR0603]
R267  100/NC  [SR0603]
sheet SHEET_15
C32  330N  [HSC0402]
C33  330N  [HSC0402]
C54  47PF  [SC0402]
C55  47PF  [SC0402]
C140  1NF  [SC0402]
C158  100NF  [SC0402]
C316  680PF  [SC0402]
C317  680PF  [SC0402]
C320  10UF  [SC0603]
C339  1NF  [SC0402]
C350  2.2UF  [SC0603]
C351  2.2UF  [SC0603]
C363  10UF/NC  [SC0603]
R19  75K  [SR0603]
R20  75K  [SR0603]
R27  5.1K  [SR0603]
R28  5.1K  [SR0603]
R49  0  [SR0402]
R50  470K  [SR0402]
R57  2.2K  [SR0402]
R66  470K  [SR0402]
R72  560  [HSR0402]
R74  560  [HSR0402]
R91  5.6K  [SR0402]
R145  100K/NC  [SR0402]
R146  100K/NC  [SR0402]
R179  10  [SR0603]
R183  470K  [SR0402]
R193  20K  [SR0402]
R194  20K  [SR0402]
U5  SGM8903  [SGM8903]
sheet SHEET_16
C23  1NF  [SC1206]
C153  100NF  [SC0402]
C154  100NF  [SC0402]
C297  10NF/NC  [SC0402]
C307  10NF/NC  [SC0402]
J18  WBC1X41  [WBC0104-49T]
J25  MJ8-L  [MJ8-RLY]
R26  4.7K  [SR0402]
R30  4.7K  [SR0402]
R61  10  [SR0402]
R62  10  [SR0402]
R63  10  [SR0402]
R64  10  [SR0402]
R67  330  [SR0402]
R79  330  [SR0402]
R135  10K  [SR0402]
R136  10K  [SR0402]
R269  75  [SR0805]
R270  75  [SR0805]
R271  75  [SR0805]
R272  75  [SR0805]
T2  000-7090-37R  [STFM16-50-285]
U8  NC  [RN8-0402]
sheet SHEET_17
C17  180PF  [SC0402]
C79  180PF  [SC0402]
C80  100PF  [SC0402]
D9  D2-3_A  [SOT23]
J34  MIC6M2_M  [VAF6-1107]
L6  220NH  [SL0402]
R9  75  [SR0402]
sheet SHEET_18
C149  100NF  [SC0402]
C150  100NF  [SC0402]
D19  D_A  [HSOD323A]
D20  D_A  [HSOD323A]
J26  0  [WBC0119-20R-A]
R8  47K  [SR0402]
R186  2K  [SR0402]
R187  2K  [SR0402]
R268  27K  [SR0402]
U4  CS0806U  [SOT23A-6L]
U23  CS0806S  [DFN2510P10E]
U24  CS0806S  [DFN2510P10E]

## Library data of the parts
C63 C87 C93 C103 C105 C123 C124 C223-C240 C258 C308 C323 C324 = C: %182%%238%%182%%168%%185%%164%%215%%247%%181%%231%%209%%185%(V): 10; %195%%232%%202%%246%: SMD陶瓷电容-10V-100NF-+/-10%-X5R-0402; %208%%161%%192%%224%%195%%251%%179%%198%: SMD陶瓷电容; CODE: 8070561; COMPONENT_HIGH_MAX: 0.55MM; DEVICE: C0402C104K8PAC_7867
C115 C314 = C: %182%%238%%182%%168%%185%%164%%215%%247%%181%%231%%209%%185%(V): 50; %195%%232%%202%%246%: SMD陶瓷电容-50V-1NF-+/-10%-X7R-0402-BT; %208%%161%%192%%224%%195%%251%%179%%198%: SMD陶瓷电容; CODE: 8070531; COMPONENT_HIGH_MAX: 0.56MM; DEVICE: 04025C102KAT2A
C319 = C: %182%%238%%182%%168%%185%%164%%215%%247%%181%%231%%209%%185%(V): 6.3; %195%%232%%202%%246%: SMD陶瓷电容-6.3V-10000NF-+/-10%-X5R-0805-TS16949; %208%%161%%192%%224%%195%%251%%179%%198%: SMD陶瓷电容; CODE: 8070565; COMPONENT_HIGH_MAX: 1.45MM; DEVICE: CEJMK212BJ106KD_T
R17 = R: %182%%238%%182%%168%%185%%166%%194%%202%(W): 0.06; %195%%232%%202%%246%: 片式厚膜电阻器-0.0625W-200OHM-+/-5%-0402-BT; %208%%161%%192%%224%%195%%251%%179%%198%: 片式厚膜电阻器; %215%%232%%214%%181%%212%%202%%208%%237%%198%%171%%178%%238%: +/-5%; CODE: 7090863; COMPONENT_HIGH_MAX: 0.4MM; DEVICE: RK73B1ETTP201J
R71 = R: %182%%238%%182%%168%%185%%166%%194%%202%(W): 0.06; %195%%232%%202%%246%: 片式厚膜电阻器-0.0625W-240OHM-+/- 1%-0402-BT; %208%%161%%192%%224%%195%%251%%179%%198%: 片式厚膜电阻器; %215%%232%%214%%181%%212%%202%%208%%237%%198%%171%%178%%238%: +/- 1%; CODE: 7091782; COMPONENT_HIGH_MAX: 0.4MM; DEVICE: RC0402FR_07240RL
R78 R84 R92 R93 = R: %182%%238%%182%%168%%185%%166%%194%%202%(W): 0.06; %195%%232%%202%%246%: 片式厚膜电阻器-0.0625W-1000OHM-+/-1%-0402-BT; %208%%161%%192%%224%%195%%251%%179%%198%: 片式厚膜电阻器; %215%%232%%214%%181%%212%%202%%208%%237%%198%%171%%178%%238%: +/-1%; CODE: 7091282; COMPONENT_HIGH_MAX: 0.4MM; DEVICE: RC0402FR_071KL
U6 = MT41J256M16RE-15E-D_1: %195%%232%%202%%246%: DDR3 DRAM-4GBIT-800MHZ-16BIT-1.5V-FBGA96(无铅); %208%%161%%192%%224%%195%%251%%179%%198%: DDR3 DRAM; CODE: 40020173; COMPONENT_HIGH_MAX: -99999999MM; DEVICE: H5TQ4G63MFR_PBC_A
C36 = C: %182%%238%%182%%168%%185%%164%%215%%247%%181%%231%%209%%185%(V): 25; %195%%232%%202%%246%: SMD陶瓷电容-25V-1000NF-+/-10%-X7R-0603; %208%%161%%192%%224%%195%%251%%179%%198%: SMD陶瓷电容; CODE: 8070962; COMPONENT_HIGH_MAX: 0.9MM; DEVICE: CETMK107B7105KA_T
C88 = CP: %182%%238%%182%%168%%185%%164%%215%%247%%181%%231%%209%%185%(V): 16; %195%%232%%202%%246%: 非固体SMD铝电容-16V-100UF-+/-20%-6.3*5.4MM-极性-105DEGC-1000H-片式,温度敏感器件-工艺耐温250DEGC,5S; %208%%161%%192%%224%%195%%251%%179%%198%: 非固体SMD铝电容; CODE: 8010269; COMPONENT_HIGH_MAX: 5.7MM; DEVICE: UWT1C101MCL1GB
C142 C143 C153 C154 C158 = C: %182%%238%%182%%168%%185%%164%%215%%247%%181%%231%%209%%185%(V): 16; %195%%232%%202%%246%: SMD陶瓷电容-16V-100NF-±10%-X7R-0402; %208%%161%%192%%224%%195%%251%%179%%198%: SMD陶瓷电容; CODE: 8070614; COMPONENT_HIGH_MAX: 0.6MM; DEVICE: RMEMK105BJ104KV_FR
C275 = C: %182%%238%%182%%168%%185%%164%%215%%247%%181%%231%%209%%185%(V): 6.3; %195%%232%%202%%246%: SMD陶瓷电容-6.3V-2200NF-+/-10%-X5R-0603; %208%%161%%192%%224%%195%%251%%179%%198%: SMD陶瓷电容; CODE: 8070563; COMPONENT_HIGH_MAX: 0.95MM; DEVICE: CM105X5R225K06AT
D2 D19 D20 = D_A: %195%%232%%202%%246%: 肖特基二极管-10V-3A-0.24V-SOD323-BT; %208%%161%%192%%224%%195%%251%%179%%198%: 肖特基二极管; CODE: 15010252; COMPONENT_HIGH_MAX: 1.1MM; DEVICE: BAT60BE6327
R8 R12 R29 R58 R151-R156 R176 R177 R188 R189 R202 R203 = R: %182%%238%%182%%168%%185%%166%%194%%202%(W): 0.06; %195%%232%%202%%246%: 片式厚膜电阻器-0.0625W-47000OHM-+/-5%-0402-ELOM; %208%%161%%192%%224%%195%%251%%179%%198%: 片式厚膜电阻器; %215%%232%%214%%181%%212%%202%%208%%237%%198%%171%%178%%238%: +/-5%; CODE: 7090819; DEVICE: RC0402JR_0747K
R68 R80 = R: %182%%238%%182%%168%%185%%166%%194%%202%(W): 0.06; %195%%232%%202%%246%: 片式厚膜电阻器-0.0625W-0OHM-< 50MOHM-0402-1A-BT; %208%%161%%192%%224%%195%%251%%179%%198%: 片式厚膜电阻器; %215%%232%%214%%181%%212%%202%%208%%237%%198%%171%%178%%238%: < 50MOHM; CODE: 7090800; COMPONENT_HIGH_MAX: 0.4MM; DEVICE: RC0402JR_070R
R89 = R: %182%%238%%182%%168%%185%%166%%194%%202%(W): 0.06; %195%%232%%202%%246%: 片式厚膜电阻器-0.0625W-1000OHM-±5%-0402; %208%%161%%192%%224%%195%%251%%179%%198%: 片式厚膜电阻器; %215%%232%%214%%181%%212%%202%%208%%237%%198%%171%%178%%238%: ±5%; CODE: 7090809; COMPONENT_HIGH_MAX: 0.4MM; DEVICE: RC0402JR_071KL
R94 = R: %182%%238%%182%%168%%185%%166%%194%%202%(W): 0.13; %195%%232%%202%%246%: 片式厚膜电阻器-0.125W-0OHM-<50MOHM-0805-2A-BT; %208%%161%%192%%224%%195%%251%%179%%198%: 片式厚膜电阻器; %215%%232%%214%%181%%212%%202%%208%%237%%198%%171%%178%%238%: <50MOHM; CODE: 7090299; COMPONENT_HIGH_MAX: 0.65MM; DEVICE: RC0805JR_070RL
R96 R186 R187 = R: %182%%238%%182%%168%%185%%166%%194%%202%(W): 0.06; %195%%232%%202%%246%: 片式厚膜电阻器-0.0625W-2000OHM-+/-1%-0402-BT; %208%%161%%192%%224%%195%%251%%179%%198%: 片式厚膜电阻器; %215%%232%%214%%181%%212%%202%%208%%237%%198%%171%%178%%238%: +/-1%; CODE: 7091354; COMPONENT_HIGH_MAX: 0.4MM; DEVICE: RC_02W2001FT
R11 R15 R212 = R: %182%%238%%182%%168%%185%%166%%194%%202%(W): 0.06; %195%%232%%202%%246%: 片式厚膜电阻器-0.0625W-10000OHM-+/-5%-0402-BT; %208%%161%%192%%224%%195%%251%%179%%198%: 片式厚膜电阻器; %215%%232%%214%%181%%212%%202%%208%%237%%198%%171%%178%%238%: +/-5%; CODE: 7090815; DEVICE: RC_02W103JT
R26 R30 R215 = R: %182%%238%%182%%168%%185%%166%%194%%202%(W): 0.06; %195%%232%%202%%246%: 片式厚膜电阻器-0.0625W-4700OHM-+/-5%-0402; %208%%161%%192%%224%%195%%251%%179%%198%: 片式厚膜电阻器; %215%%232%%214%%181%%212%%202%%208%%237%%198%%171%%178%%238%: +/-5%; CODE: 7090793; COMPONENT_HIGH_MAX: 0.4MM; DEVICE: RK73B1ELTP472J
U19 = MLC_NAND_0: CODE: *
U22 = N_1: CODE: 40060446; CaptureCellPackProp: NA
C21 C47 C320 C363 = C: %182%%238%%182%%168%%185%%164%%215%%247%%181%%231%%209%%185%(V): 6.3; %195%%232%%202%%246%: SMD陶瓷电容-6.3V-10000NF-+/-20%-X5R-0603-BT,TS16949; %208%%161%%192%%224%%195%%251%%179%%198%: SMD陶瓷电容; CODE: 8070649; COMPONENT_HIGH_MAX: 0.9MM; DEVICE: C1608X5R0J106MT0A0E
C29 C38 = C: %182%%238%%182%%168%%185%%164%%215%%247%%181%%231%%209%%185%(V): 6.3; %195%%232%%202%%246%: SMD陶瓷电容-6.3V-22000NF-+/-20%-X5R-0805-08070784编码拆分供华为技术使用; %208%%161%%192%%224%%195%%251%%179%%198%: SMD陶瓷电容; CODE: 8071114; COMPONENT_HIGH_MAX: 1.35MM; DEVICE: C2012X5R0J226MT000N
C50 C60 C61 C135 = C: %182%%238%%182%%168%%185%%164%%215%%247%%181%%231%%209%%185%(V): 50; %195%%232%%202%%246%: SMD陶瓷电容-50V-0.001NF-+/-0.1PF-NPO-0402-BT; %208%%161%%192%%224%%195%%251%%179%%198%: SMD陶瓷电容; CODE: 8070578; COMPONENT_HIGH_MAX: 0.55MM; DEVICE: GRM1555C1H1R0B
C56 C106 C118 C119 C122 C263 = C: %182%%238%%182%%168%%185%%164%%215%%247%%181%%231%%209%%185%(V): 50; %195%%232%%202%%246%: SMD陶瓷电容-50V-100NF-±10%-X7R-0603; %208%%161%%192%%224%%195%%251%%179%%198%: SMD陶瓷电容; CODE: 8070627; COMPONENT_HIGH_MAX: 0.9MM; DEVICE: C1608X7R1H104KT000N
C139 C141 = C: %182%%238%%182%%168%%185%%164%%215%%247%%181%%231%%209%%185%(V): 50; %195%%232%%202%%246%: SMD陶瓷电容-50V-0.003NF-+/-0.25PF-NPO-0402; %208%%161%%192%%224%%195%%251%%179%%198%: SMD陶瓷电容; CODE: 8070636; COMPONENT_HIGH_MAX: 0.55MM; DEVICE: GRM1555C1H3R0CZ01D
D1 D6 = ULCE0505A015FR
J2 = WIFI_2T2R
J4 J5 = COX-3_A: %195%%232%%202%%246%: 射频连接器-同轴连接器-50OHM-直式-MALE-SMT-终端专用-终端专用; %208%%161%%192%%224%%195%%251%%179%%198%: 射频连接器; CODE: 14240060; COMPONENT_HIGH_MAX: 1.45MM; DEVICE: 51_3612_50_H
J12 J13 = USBA_0: CODE: 14080105
L1 L7 = L: %195%%232%%202%%246%: 贴片电感器-0.001UH-5％-0.045OHM-1.36A-15DEGC-0402; %208%%161%%192%%224%%195%%251%%179%%198%: 贴片电感器; CODE: 10031232; COMPONENT_HIGH_MAX: 0.66MM; DEVICE: 0402CS_1N0XJLW
LB2 LB3 = LB: %195%%232%%202%%246%: EMI磁珠-30OHM-0.05OHM-0.4A-0603-; %208%%161%%192%%224%%195%%251%%179%%198%: EMI磁珠; CODE: 10070003; COMPONENT_HIGH_MAX: 0.95MM; DEVICE: MGLB1608_030T_LF
LB4 = LB: %195%%232%%202%%246%: EMI磁珠-+/-25%-220OHM-0.05OHM-2A-0805; %208%%161%%192%%224%%195%%251%%179%%198%: EMI磁珠; CODE: 10070012; COMPONENT_HIGH_MAX: 1.05MM; DEVICE: MGLB2012_220T_LF
R47 R48 = R: %182%%238%%182%%168%%185%%166%%194%%202%(W): 0.06; %195%%232%%202%%246%: 片式厚膜电阻器-0.0625W-22000OHM-+/-1%-0402; %208%%161%%192%%224%%195%%251%%179%%198%: 片式厚膜电阻器; %215%%232%%214%%181%%212%%202%%208%%237%%198%%171%%178%%238%: +/-1%; CODE: 7090798; COMPONENT_HIGH_MAX: 0.4MM; DEVICE: RK73H1ELTP2202F
U2 = CDT-CELKF04
U7 = CDT-CELKF10_0
U10 U12 = ETA6010_1
C131 = C: %182%%238%%182%%168%%185%%164%%215%%247%%181%%231%%209%%185%(V): 10; %195%%232%%202%%246%: SMD陶瓷电容-10V-1000NF-+/-10%-X5R-0402-BT,TS16949; %208%%161%%192%%224%%195%%251%%179%%198%: SMD陶瓷电容; CODE: 8070612; COMPONENT_HIGH_MAX: 0.55MM; DEVICE: CV05X5R105K10AH
C149 C150 C177 = C: %182%%238%%182%%168%%185%%164%%215%%247%%181%%231%%209%%185%(V): 16; %195%%232%%202%%246%: SMD陶瓷电容-16V-100NF-+/-10%-X7R-0402-BT; %208%%161%%192%%224%%195%%251%%179%%198%: SMD陶瓷电容; CODE: 8070614; COMPONENT_HIGH_MAX: 0.6MM; DEVICE: RMEMK105BJ104KV_FR
C350 C351 C391 = C: %182%%238%%182%%168%%185%%164%%215%%247%%181%%231%%209%%185%(V): 10; %195%%232%%202%%246%: SMD陶瓷电容-10V-2200NF-+/-10%-X5R-0603; %208%%161%%192%%224%%195%%251%%179%%198%: SMD陶瓷电容; CODE: 8070573; COMPONENT_HIGH_MAX: 0.9MM; DEVICE: GRM188R61A225KE34D
D3 = IRM-3638A_7: %195%%232%%202%%246%: 红外遥控接收头-5V-0.001A-0.015KM-38KHZ-940NM-7*8*3.75; %208%%161%%192%%224%%195%%251%%179%%198%: 红外遥控接收头; COMPONENT_HIGH_MAX: 6.95MM; DEVICE: TSOP4838
J21 = MMC10S5: %195%%232%%202%%246%: 板卡座类连接器-MICRO-SD卡座-8PIN-PUSH-PUSH-1.1MM-无锁扣-无-1MM-厚度1.45MM-终端专用; CODE: 14240249; COMPONENT_HIGH_MAX: 1.55MM; DEVICE: 5031820832
LED1 = LED2-3_E: %195%%232%%202%%246%: 发光二极管-0.25CD-红绿625NM/570NM-25MA-插装-共阴-终端专用-00500098; CODE: 15020190; COMPONENT_HIGH_MAX: 7.2MM; DEVICE: 209_3SYGSURC_S530_A3HW
Q1 Q2 Q5 = NPN-BEC_0: %195%%232%%202%%246%: 三极管-NPN-45V-100MA-225MW-200MV@100MA-SOT-23-180@2MA; %208%%161%%192%%224%%195%%251%%179%%198%: 三极管; CODE: 15050206; COMPONENT_HIGH_MAX: 1.26MM; DEVICE: BC847AE6327
Q15 = FETP-GSD_1: %195%%232%%202%%246%: MOSFET-P沟道--8V--3A-50MOHM--8V-SOT23; %208%%161%%192%%224%%195%%251%%179%%198%: MOSFET; CODE: 15060134; COMPONENT_HIGH_MAX: 1.11MM; DEVICE: IRLML6401TR
R2 R34 R67 R79 = R: %182%%238%%182%%168%%185%%166%%194%%202%(W): 0.06; %195%%232%%202%%246%: 片式厚膜电阻器-0.0625W-330OHM-+/-1%-0402-BT; %208%%161%%192%%224%%195%%251%%179%%198%: 片式厚膜电阻器; %215%%232%%214%%181%%212%%202%%208%%237%%198%%171%%178%%238%: +/-1%; CODE: 7091333; COMPONENT_HIGH_MAX: 0.4MM; DEVICE: RC_02W3300FT
R3 = R: %182%%238%%182%%168%%185%%166%%194%%202%(W): 0.06; %195%%232%%202%%246%: 片式厚膜电阻器-0.0625W-1000OHM-+/-5%-0402-BT; %208%%161%%192%%224%%195%%251%%179%%198%: 片式厚膜电阻器; %215%%232%%214%%181%%212%%202%%208%%237%%198%%171%%178%%238%: +/-5%; CODE: 7090809; COMPONENT_HIGH_MAX: 0.4MM; DEVICE: RC0402JR_071KL
R22 R140 = R: %182%%238%%182%%168%%185%%166%%194%%202%(W): 0.06; %195%%232%%202%%246%: 片式厚膜电阻器-0.0625W-10000OHM-+/-5%-0402-BT; %208%%161%%192%%224%%195%%251%%179%%198%: 片式厚膜电阻器; %215%%232%%214%%181%%212%%202%%208%%237%%198%%171%%178%%238%: +/-5%; CODE: 7090815; COMPONENT_HIGH_MAX: 0.4MM; DEVICE: RC_02W103JT
R31 R51 = R: %182%%238%%182%%168%%185%%166%%194%%202%(W): 0.06; %195%%232%%202%%246%: 片式厚膜电阻器-0.0625W-4700OHM-+/-5%-0402-BT; %208%%161%%192%%224%%195%%251%%179%%198%: 片式厚膜电阻器; %215%%232%%214%%181%%212%%202%%208%%237%%198%%171%%178%%238%: +/-5%; CODE: 7090793; COMPONENT_HIGH_MAX: 0.4MM; DEVICE: RK73B1ELTP472J
R76 R77 = R: %182%%238%%182%%168%%185%%166%%194%%202%(W): 0.1; %195%%232%%202%%246%: 片式厚膜电阻器-0.1W-10000OHM-+/-1%-0603; %208%%161%%192%%224%%195%%251%%179%%198%: 片式厚膜电阻器; %215%%232%%214%%181%%212%%202%%208%%237%%198%%171%%178%%238%: +/-1%; CODE: 7090889; COMPONENT_HIGH_MAX: 0.55MM; DEVICE: RC_03K1002FT
R86 = R: %182%%238%%182%%168%%185%%166%%194%%202%(W): 0.1; %195%%232%%202%%246%: 片式厚膜电阻器-0.1W-0OHM-<50MOHM-0603-1A-BT,TS16949; %208%%161%%192%%224%%195%%251%%179%%198%: 片式厚膜电阻器; %215%%232%%214%%181%%212%%202%%208%%237%%198%%171%%178%%238%: <50MOHM; CODE: 7090522; COMPONENT_HIGH_MAX: 0.55MM; DEVICE: RC0603JR_070RL
R149 = R: %182%%238%%182%%168%%185%%166%%194%%202%(W): 0.1; %195%%232%%202%%246%: 片式厚膜电阻器-0.1W-4700OHM-+/-5%-0603-抗硫化; %208%%161%%192%%224%%195%%251%%179%%198%: 片式厚膜电阻器; %215%%232%%214%%181%%212%%202%%208%%237%%198%%171%%178%%238%: +/-5%; CODE: 7090246; DEVICE: RC0603JR_074K7
R9 R178 = R: %182%%238%%182%%168%%185%%166%%194%%202%(W): 0.06; %195%%232%%202%%246%: 片式厚膜电阻器-0.0625W-75OHM-+/-1%-0402; %208%%161%%192%%224%%195%%251%%179%%198%: 片式厚膜电阻器; %215%%232%%214%%181%%212%%202%%208%%237%%198%%171%%178%%238%: +/-1%; CODE: 7091321; COMPONENT_HIGH_MAX: 0.4MM; DEVICE: RC_02W750FT
R210 = R: %182%%238%%182%%168%%185%%166%%194%%202%(W): 0.1; %195%%232%%202%%246%: 片式厚膜电阻器-0.1W-1000OHM-+/-5%-0603; %208%%161%%192%%224%%195%%251%%179%%198%: 片式厚膜电阻器; %215%%232%%214%%181%%212%%202%%208%%237%%198%%171%%178%%238%: +/-5%; CODE: 7090277; COMPONENT_HIGH_MAX: 0.55MM; DEVICE: RC0603JR_071K
R267 = R: %182%%238%%182%%168%%185%%166%%194%%202%(W): 0.06; %195%%232%%202%%246%: 片式厚膜电阻器-0.1W-100OHM-±5%-0603; %208%%161%%192%%224%%195%%251%%179%%198%: 片式厚膜电阻器; %215%%232%%214%%181%%212%%202%%208%%237%%198%%171%%178%%238%: ±5%; CODE: 7090269; COMPONENT_HIGH_MAX: 0.55MM; DEVICE: RC0603JR_07100RL
C32 C33 = C: %195%%232%%202%%246%: SMD陶瓷电容-6.3V-330NF-+/-10%-X5R-0402-终端专用; %208%%161%%192%%224%%195%%251%%179%%198%: SMD陶瓷电容; CODE: 8070953; COMPONENT_HIGH_MAX: 0.55MM; DEVICE: C1005X5R0J334K
C54 C55 = C: %182%%238%%182%%168%%185%%164%%215%%247%%181%%231%%209%%185%(V): 50; %195%%232%%202%%246%: SMD陶瓷电容-50V-0.047NF-+/-5%-NP0-0402; %208%%161%%192%%224%%195%%251%%179%%198%: SMD陶瓷电容; CODE: 8070549; COMPONENT_HIGH_MAX: 0.55MM; DEVICE: C0402C470J5GAC_7867
C140 C339 = C: %182%%238%%182%%168%%185%%164%%215%%247%%181%%231%%209%%185%(V): 50; %195%%232%%202%%246%: SMD陶瓷电容-50V-1NF-+/-10%-X7R-0402-BT; %208%%161%%192%%224%%195%%251%%179%%198%: SMD陶瓷电容; CODE: 8070531; COMPONENT_HIGH_MAX: 0.55MM; DEVICE: 04025C102KAT2A
C316 C317 = C: %182%%238%%182%%168%%185%%164%%215%%247%%181%%231%%209%%185%(V): 50; %195%%232%%202%%246%: SMD陶瓷电容-50V-0.68NF-+/-5%-NP0-0402-供电专用-供电专用; %208%%161%%192%%224%%195%%251%%179%%198%: SMD陶瓷电容; CODE: 8070853; COMPONENT_HIGH_MAX: 0.55MM; DEVICE: C0402C681J5GAC7867
R19 R20 = R: %182%%238%%182%%168%%185%%166%%194%%202%(W): 0.1; %195%%232%%202%%246%: 片式厚膜电阻器-0.1W-75000OHM-+/-1% -0603; %208%%161%%192%%224%%195%%251%%179%%198%: 片式厚膜电阻器; %215%%232%%214%%181%%212%%202%%208%%237%%198%%171%%178%%238%: +/-1%; CODE: 7091238; COMPONENT_HIGH_MAX: 0.55MM; DEVICE: RK73H1JTTD7502F
R27 R28 = R: %182%%238%%182%%168%%185%%166%%194%%202%(W): 0.1; %195%%232%%202%%246%: 片式厚膜电阻器-0.1W-5100OHM-+/-1%-0603; %208%%161%%192%%224%%195%%251%%179%%198%: 片式厚膜电阻器; %215%%232%%214%%181%%212%%202%%208%%237%%198%%171%%178%%238%: +/-1%; CODE: 7091295; COMPONENT_HIGH_MAX: 0.55MM; DEVICE: RC0603FR_075K1L
R49 = R: %182%%238%%182%%168%%185%%166%%194%%202%(W): 0.06; %195%%232%%202%%246%: 片式厚膜电阻器-0.0625W-0OHM-< 50MOHM-0402-1A-BT; %208%%161%%192%%224%%195%%251%%179%%198%: 片式厚膜电阻器; %215%%232%%214%%181%%212%%202%%208%%237%%198%%171%%178%%238%: < 50MOHM; CODE: 7090800; DEVICE: RC0402JR_070R
R50 R183 = R: %182%%238%%182%%168%%185%%166%%194%%202%(W): 0.06; %195%%232%%202%%246%: 片式厚膜电阻器-0.0625W-470000OHM-±1%-0402; %208%%161%%192%%224%%195%%251%%179%%198%: 片式厚膜电阻器; %215%%232%%214%%181%%212%%202%%208%%237%%198%%171%%178%%238%: ±1%; CODE: 7090855; COMPONENT_HIGH_MAX: 0.4MM; DEVICE: RK73H1ETTP4703F
R57 = R: %182%%238%%182%%168%%185%%166%%194%%202%(W): 0.06; %195%%232%%202%%246%: 片式厚膜电阻器-0.0625W-2200OHM-+/-1%-0402--供电专用-07090810-供电专用; %208%%161%%192%%224%%195%%251%%179%%198%: 片式厚膜电阻器; %215%%232%%214%%181%%212%%202%%208%%237%%198%%171%%178%%238%: +/-1%; CODE: 7091537; COMPONENT_HIGH_MAX: 0.4MM; DEVICE: RC0402FR_072K2L2
R66 = R: %182%%238%%182%%168%%185%%166%%194%%202%(W): 0.06; %195%%232%%202%%246%: 片式厚膜电阻器-0.0625W-470000OHM-+/-1%-0402; %208%%161%%192%%224%%195%%251%%179%%198%: 片式厚膜电阻器; %215%%232%%214%%181%%212%%202%%208%%237%%198%%171%%178%%238%: +/-1%; CODE: 7090855; COMPONENT_HIGH_MAX: 0.4MM; DEVICE: RK73H1ETTP4703F
R72 R74 = R: %195%%232%%202%%246%: 片式厚膜电阻器-0.0625W-560OHM-+/-5%-0402-终端专用-终端专用; %208%%161%%192%%224%%195%%251%%179%%198%: 片式厚膜电阻器; CODE: 7091285; COMPONENT_HIGH_MAX: 0.4MM; DEVICE: RC0402JR_07560RL
R91 = R: %182%%238%%182%%168%%185%%166%%194%%202%(W): 0.06; %195%%232%%202%%246%: 片式厚膜电阻器-0.0625W-5600OHM-+/-1%-0402-BT; %208%%161%%192%%224%%195%%251%%179%%198%: 片式厚膜电阻器; %215%%232%%214%%181%%212%%202%%208%%237%%198%%171%%178%%238%: +/-1%; CODE: 7091275; COMPONENT_HIGH_MAX: 0.4MM; DEVICE: RK73H1ETTP5601F
R145 R146 = R: %182%%238%%182%%168%%185%%166%%194%%202%(W): 0.06; %195%%232%%202%%246%: 片式厚膜电阻器-0.0625W-100000OHM-+/-5%-0402-BT; %208%%161%%192%%224%%195%%251%%179%%198%: 片式厚膜电阻器; %215%%232%%214%%181%%212%%202%%208%%237%%198%%171%%178%%238%: +/-5%; CODE: 7090831; COMPONENT_HIGH_MAX: 0.4MM; DEVICE: RK73B1ELTP104J
R179 = R: %182%%238%%182%%168%%185%%166%%194%%202%(W): 0.1; %195%%232%%202%%246%: 片式厚膜电阻器-0.1W-10OHM-+/-5%-0603-TS16949; %208%%161%%192%%224%%195%%251%%179%%198%: 片式厚膜电阻器; %215%%232%%214%%181%%212%%202%%208%%237%%198%%171%%178%%238%: +/-5%; CODE: 7090264; COMPONENT_HIGH_MAX: 0.55MM; DEVICE: RC0603JR_0710R
R193 R194 = R: %182%%238%%182%%168%%185%%166%%194%%202%(W): 0.06; %195%%232%%202%%246%: 片式厚膜电阻器-0.0625W-20000OHM-+/-1%-0402-TS16949; %208%%161%%192%%224%%195%%251%%179%%198%: 片式厚膜电阻器; %215%%232%%214%%181%%212%%202%%208%%237%%198%%171%%178%%238%: +/-1%; CODE: 7091374; COMPONENT_HIGH_MAX: 0.4MM; DEVICE: RC_02W2002FT
U5 = SGM8903
C23 = C: %182%%238%%182%%168%%185%%164%%215%%247%%181%%231%%209%%185%(V): 2000; %195%%232%%202%%246%: SMD陶瓷电容-2000V-1NF-+/-20%-X7R-1206; %208%%161%%192%%224%%195%%251%%179%%198%: SMD陶瓷电容; CODE: 8070439; COMPONENT_HIGH_MAX: 1.52MM; DEVICE: 1206GC102MAT1A
C297 C307 = C: %182%%238%%182%%168%%185%%164%%215%%247%%181%%231%%209%%185%(V): 16; %195%%232%%202%%246%: SMD陶瓷电容-16V-10NF-+/-10%-X7R-0402-BT,TS16949; %208%%161%%192%%224%%195%%251%%179%%198%: SMD陶瓷电容; CODE: 8070449; COMPONENT_HIGH_MAX: 0.55MM; DEVICE: GRM155R71C103KA01D
J18 = WBC1X41_0: %195%%232%%202%%246%: 普通插座-4PIN-单排-直式-1.25MM-2MM-THT-1A; %208%%161%%192%%224%%195%%251%%179%%198%: 普通插座; CODE: 14100167; COMPONENT_HIGH_MAX: 4.2MM; DEVICE: SDW12501_4A_HW
J25 = MJ8-L_0: %195%%232%%202%%246%: 网口连接器-单排-单端口-8PIN-8BIT-非屏蔽-模型插座/侧面插入型-引脚长2.54MM-带固定脚/带灯; %208%%161%%192%%224%%195%%251%%179%%198%: 网口连接器; COMPONENT_HIGH_MAX: 13.2MM; DEVICE: 406533_1
R61-R64 = R: %182%%238%%182%%168%%185%%166%%194%%202%(W): 0.06; %195%%232%%202%%246%: 片式厚膜电阻器-0.0625W-10OHM-+/-5%-0402; %208%%161%%192%%224%%195%%251%%179%%198%: 片式厚膜电阻器; %215%%232%%214%%181%%212%%202%%208%%237%%198%%171%%178%%238%: +/-5%; CODE: 7090730; COMPONENT_HIGH_MAX: 0.4MM; DEVICE: RC0402JR_0710R
R135 R136 = R: %182%%238%%182%%168%%185%%166%%194%%202%(W): 0.06; %195%%232%%202%%246%: 片式厚膜电阻器-0.0625W-10000OHM-±5%-0402; %208%%161%%192%%224%%195%%251%%179%%198%: 片式厚膜电阻器; %215%%232%%214%%181%%212%%202%%208%%237%%198%%171%%178%%238%: ±5%; CODE: 7090815; COMPONENT_HIGH_MAX: 0.4MM; DEVICE: RC_02W103JT
R269-R272 = R: %182%%238%%182%%168%%185%%166%%194%%202%(W): 0.13; %195%%232%%202%%246%: 片式厚膜电阻器-0.125W-75OHM-±1%-0805; %208%%161%%192%%224%%195%%251%%179%%198%: 片式厚膜电阻器; %215%%232%%214%%181%%212%%202%%208%%237%%198%%171%%178%%238%: ±1%; CODE: 7090362; DEVICE: RC0805FR_0775R
T2 = 000-7090-37R_1: %195%%232%%202%%246%: LAN变压器-1CT:1CT-0.35MH-0UH-1路-2变压器-100BASE-T接口模块-SMT; %208%%161%%192%%224%%195%%251%%179%%198%: LAN变压器; CODE: 9050085; COMPONENT_HIGH_MAX: 6.2MM; DEVICE: H1102T
U8 = CS2203-25
C17 C79 = C: %182%%238%%182%%168%%185%%164%%215%%247%%181%%231%%209%%185%(V): 50; %195%%232%%202%%246%: SMD陶瓷电容-50V-0.18NF-+/-5%-NPO-0402; %208%%161%%192%%224%%195%%251%%179%%198%: SMD陶瓷电容; CODE: 8070637; COMPONENT_HIGH_MAX: 0.55MM; DEVICE: CC0402JRNPO9BB181
C80 = C: %182%%238%%182%%168%%185%%164%%215%%247%%181%%231%%209%%185%(V): 50; %195%%232%%202%%246%: SMD陶瓷电容-50V-0.1NF-±5%-NPO-0402; %208%%161%%192%%224%%195%%251%%179%%198%: SMD陶瓷电容; CODE: 8070450; COMPONENT_HIGH_MAX: 0.55MM; DEVICE: 04025A101JAT2A
D9 = D2-3_A: %195%%232%%202%%246%: 开关二极管-70V-200MA-1.25V-6NS-串联-SOT-23-2 FIT; %208%%161%%192%%224%%195%%251%%179%%198%: 开关二极管; CODE: 15010042; COMPONENT_HIGH_MAX: 1.26MM; DEVICE: BAV99B5003
J34 = MIC6M2_M_0: %195%%232%%202%%246%: 耳机连接器-3.5MM-5PIN-弯式-THT-00486672; CODE: 14240414; COMPONENT_HIGH_MAX: 5MM; DEVICE: 8967_3506ADT_M_A
L6 = L: %195%%232%%202%%246%: 贴片电感器-0.22UH-+/-5%-3.77OHM-0.3A-0402; %208%%161%%192%%224%%195%%251%%179%%198%: 贴片电感器; CODE: 10031264; COMPONENT_HIGH_MAX: 0.55MM; DEVICE: LGHK1005R22J_T
J26 = WBC1X19S4M2_0: %195%%232%%202%%246%: IO连接器-HDMI 母座-19PIN-弯式-SMT带DIP脚-终端专用; %208%%161%%192%%224%%195%%251%%179%%198%: IO连接器; CODE: 14240146; COMPONENT_HIGH_MAX: 6.38MM; DEVICE: 1827059_3
R268 = R: %182%%238%%182%%168%%185%%166%%194%%202%(W): 0.06; %195%%232%%202%%246%: 片式厚膜电阻器-0.0625W-27000OHM-+/-5%-0402; %208%%161%%192%%224%%195%%251%%179%%198%: 片式厚膜电阻器; %215%%232%%214%%181%%212%%202%%208%%237%%198%%171%%178%%238%: +/-5%; CODE: 7090852; COMPONENT_HIGH_MAX: 0.4MM; DEVICE: RK73B1ETTP273J
U4 = CS0806U
U23 = CS0806S: #: 3
U24 = CS0806S

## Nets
1V5_DDR3: C103.1(A) C223.1(A) C224.1(A) C225.1(A) C226.1(A) C227.1(A) C228.1(A) C229.1(A) C230.1(A) C231.1(A) C232.1(A) C233.1(A) C234.1(A) C235.1(A) C236.1(A) C237.1(A) C238.1(A) C239.1(A) C240.1(A) C258.1(A) C319.1(A) R78.1(A) R92.1(A) U6.A1(VDDQ1) U6.A8(VDDQ2) U6.B2(VDD1) U6.C1(VDDQ3) U6.C9(VDDQ4) U6.D2(VDDQ5) U6.D9(VDD2) U6.E9(VDDQ6) U6.F1(VDDQ7) U6.G7(VDD3) U6.H2(VDDQ8) U6.H9(VDDQ9) U6.K2(VDD4) U6.K8(VDD5) U6.N1(VDD6) U6.N9(VDD7) U6.R1(VDD8) U6.R9(VDD9) ; also on sheet 9 11 15
3V3: J18.4 R2.1(A) R31.1(A) R34.1(A) R135.1(A) R136.1(A) R140.2(B) R178.2(B) ; also on sheet 10 13 14 15
3V3_MOS: C131.1(A) D2.2(A) D9.2(K) D19.2(A) J25.10 J25.12 LB4.2 Q15.2(S) R26.1(A) R30.1(A) R77.1(A) R86.1(A) R94.1(A) R155.1(A) ; also on sheet 10 11 12 13 14
3V3_MOS_FLASH: C36.1(A) C63.1(A) C88.1 C93.1(A) C105.1(A) C142.1(A) C143.1(A) C275.1(A) C323.1(A) C324.1(A) D2.1(K) R12.1(A) R29.1(A) R58.1(A) R68.2(B) R80.1(A) R94.2(B) R96.2(B) R176.1(A) R177.1(A) R188.1(A) R189.1(A) R202.1(A) R203.1(A) R212.1(A) R215.1(A) U19.1(NC1/VDD3) U19.12(VDD1) U19.24(NC15/VDD4) U19.34(NC21/VDDQ1) U19.37(VDD2) U22.AA3(VDD_4) U22.AA5(VDD_5) U22.K6(VDD_1) U22.M6(VDDF_1) U22.N5(VDDF_2) U22.T10(VDDF_3) U22.U9(VDDF_4) U22.W4(VDD_2) U22.Y4(VDD_3)
3V3_SD: C263.1(A) C391.1(A) J21.4(VDD) Q15.3(D) R86.2(B) R210.1(A)
3V3_WIFI: C21.1(A) C106.1(A) J2.5(DVDD33) LB4.1 U2.5(VDD3.3) U7.8(VDD3.3)
5V0_MOS: C56.1(A) C119.1(A) D20.2(A) LB2.2 LB3.2 R11.2(B) R15.2(B) R179.1(A) U10.1(IN) U12.1(IN) ; also on sheet 14
5V0_MOS_HDMI: C150.1(A) D20.1(K) J26.18 R186.2(B) R187.2(B) U4.5(VDD)
GND: C17.2(B) C21.2(B) C23.2(B) C29.2(B) C33.1(A) C36.2(B) C38.2(B) C47.2(B) C50.2(B) C56.2(B) C60.2(B) C61.2(B) C63.2(B) C79.2(B) C87.2(B) C88.2 C93.2(B) C105.2(B) C106.2(B) C115.2(B) C118.2(B) C119.2(B) C122.2(B) C123.2(B) C124.2(B) C135.2(B) C139.2(B) C140.2(B) C141.2(B) C142.2(B) C143.2(B) C149.2(B) C150.2(B) C153.2(B) C154.2(B) C158.2(B) C177.2(B) C224.2(B) C225.2(B) C226.2(B) C227.2(B) C228.2(B) C229.2(B) C230.2(B) C231.2(B) C232.2(B) C233.2(B) C234.2(B) C235.2(B) C236.2(B) C237.2(B) C238.2(B) C239.2(B) C240.2(B) C258.2(B) C263.2(B) C275.2(B) C297.2(B) C307.2(B) C308.2(B) C314.2(B) C316.2(B) C317.2(B) C319.2(B) C320.2(B) C323.2(B) C324.2(B) C339.2(B) C363.2(B) C391.2(B) D1.2(B) D3.2(GND) D6.2(B) D9.1(A) J2.2(GND1) J2.7(GND5) J2.9(GND3) J2.10(GND2) J2.12(GND4) J4.2 J4.3 J5.2 J5.3 J12.4 J12.5(S1) J12.6(S2) J13.4 J13.5(S1) J13.6(S2) J18.1 J21.6(VSS) J21.10(DETECT_TERM) J21.11(S1) J21.12(S2) J21.13(S3) J21.14(S4) J21.15(S5) J26.2 J26.5 J26.8 J26.11 J26.17 J26.20(S1) J26.21(S2) J26.22(S3) J26.23(S4) J34.5(P5) LED1.2(C) Q1.2(E) Q2.2(E) Q5.2(E) R8.1(A) R9.2(B) R47.1(A) R48.1(A) R50.2(B) R51.2(B) R57.2(B) R71.1(A) R84.2(B) R89.2(B) R93.2(B) R96.1(A) R145.2(B) R146.2(B) R149.2(B) R183.2(B) R210.2(B) U2.1(GND) U2.6(RFGND) U4.2(GND) U5.1(+INR) U5.4(SGND) U5.10(PGND) U5.14(+INL) U6.A9(VSS1) U6.B1(VSSQ1) U6.B3(VSS2) U6.B9(VSSQ2) U6.D1(VSSQ3) U6.D8(VSSQ4) U6.E1(VSS3) U6.E2(VSSQ5) U6.E8(VSSQ6) U6.F9(VSSQ7) U6.G1(VSSQ8) U6.G8(VSS4) U6.G9(VSSQ9) U6.J2(VSS5) U6.J8(VSS6) U6.M1(VSS7) U6.M9(VSS8) U6.P1(VSS9) U6.P9(VSS10) U6.T1(VSS11) U6.T9(VSS12) U7.1(RFGND1) U7.5(GND) U10.2(GND) U12.2(GND) U19.2(NC2/VSS3) U19.13(VSS1) U19.23(NC14/VSS4) U19.25(NC16/VSS5) U19.36(VSS2) U19.48(NC29/VSS6) U22.AA4(VSS_8) U22.AA6(VSS_9) U22.K4(VSS_1) U22.M7(VSS_2) U22.P5(VSS_3) U22.R10(VSS_4) U22.U8(VSS_5) U22.Y2(VSS_6) U22.Y5(VSS_7) U23.3(GND1) U23.8(GND2) U24.3(GND1) U24.8(GND2) ; also on sheet 9 10 11 12 13 14 15 16
VDD_AUDIO: C158.1(A) C320.1(A) R66.2(B) R91.1(A) R179.2(B) U5.9(PVDD)
ADAC_VOUTL: C350.2(B) R50.1(A) ; also on sheet 12
ADAC_VOUTR: C351.1(A) R183.1(A) ; also on sheet 12
AUDIO_L: C339.1(A) J34.3(P3) R72.2(B)
AUDIO_R: C140.1(A) J34.2(P2) R74.1(A)
CVBS: C79.1(A) C80.1(A) L6.1(A) R9.1(A) ; also on sheet 12
CVBS_OUT: C17.1(A) C80.2(B) D9.3(COM) J34.4(P4) L6.2(B)
DDR_ADDR0: U6.N3(A0) ; also on sheet 9 11
DDR_ADDR1: U6.P7(A1) ; also on sheet 9 11
DDR_ADDR2: U6.P3(A2) ; also on sheet 9 11
DDR_ADDR3: U6.N2(A3) ; also on sheet 9 11
DDR_ADDR4: U6.P8(A4) ; also on sheet 9 11
DDR_ADDR5: U6.P2(A5) ; also on sheet 9 11
DDR_ADDR6: U6.R8(A6) ; also on sheet 9 11
DDR_ADDR7: U6.R2(A7) ; also on sheet 9 11
DDR_ADDR8: U6.T8(A8) ; also on sheet 9 11
DDR_ADDR9: U6.R3(A9) ; also on sheet 9 11
DDR_ADDR10: U6.L7(A10/AP) ; also on sheet 9 11
DDR_ADDR11: U6.R7(A11) ; also on sheet 9 11
DDR_ADDR12: U6.N7(A12/BC~) ; also on sheet 9 11
DDR_ADDR13: U6.T3(A13) ; also on sheet 9 11
DDR_ADDR14: U6.T7(A14) ; also on sheet 9 11
DDR_ADDR15: U6.M7(NC5) ; also on sheet 9 11
DDR_BA0: U6.M2(BA0) ; also on sheet 9 11
DDR_BA1: U6.N8(BA1) ; also on sheet 9 11
DDR_BA2: U6.M3(BA2) ; also on sheet 9 11
DDR_CASN: U6.K3(~{CAS}) ; also on sheet 9 11
DDR_CKE: U6.K9(CKE) ; also on sheet 9 11
DDR_CLK0N: R17.2(B) U6.K7(~{CK}) ; also on sheet 9 11
DDR_CLK0P: R17.1(A) U6.J7(CK) ; also on sheet 9 11
DDR_CSN: U6.L2(~{CS}) ; also on sheet 9 11
DDR_DM2: U6.E7(LDM) ; also on sheet 11
DDR_DM3: U6.D3(UDM) ; also on sheet 11
DDR_DQ16: U6.E3(DQ0) ; also on sheet 11
DDR_DQ17: U6.F7(DQ1) ; also on sheet 11
DDR_DQ18: U6.F2(DQ2) ; also on sheet 11
DDR_DQ19: U6.F8(DQ3) ; also on sheet 11
DDR_DQ20: U6.H3(DQ4) ; also on sheet 11
DDR_DQ21: U6.H8(DQ5) ; also on sheet 11
DDR_DQ22: U6.G2(DQ6) ; also on sheet 11
DDR_DQ23: U6.H7(DQ7) ; also on sheet 11
DDR_DQ24: U6.D7(DQ8) ; also on sheet 11
DDR_DQ25: U6.C3(DQ9) ; also on sheet 11
DDR_DQ26: U6.C8(DQ10) ; also on sheet 11
DDR_DQ27: U6.C2(DQ11) ; also on sheet 11
DDR_DQ28: U6.A7(DQ12) ; also on sheet 11
DDR_DQ29: U6.A2(DQ13) ; also on sheet 11
DDR_DQ30: U6.B8(DQ14) ; also on sheet 11
DDR_DQ31: U6.A3(DQ15) ; also on sheet 11
DDR_DQS2N: U6.G3(~{LDQS}) ; also on sheet 11
DDR_DQS2P: U6.F3(LDQS) ; also on sheet 11
DDR_DQS3N: U6.B7(~{UDQS}) ; also on sheet 11
DDR_DQS3P: U6.C7(UDQS) ; also on sheet 11
DDR_ODT: U6.K1(ODT) ; also on sheet 9 11
DDR_RASN: U6.J3(~{RAS}) ; also on sheet 9 11
DDR_RESETN: C314.1(A) U6.T2(~{RESET}) ; also on sheet 9 11
DDR_VREF_B_CA: C87.1(A) C103.2(B) R92.2(B) R93.1(A) U6.M8(VREFCA)
DDR_VREF_B_DQ: C223.2(B) C308.1(A) R78.2(B) R84.1(A) U6.H1(VREFDQ)
DDR_WEN: U6.L3(~{WE}) ; also on sheet 9 11
HDMI_TX0N: J26.9 U24.2(IO2_IN) U24.9(IO2_OUT) ; also on sheet 12
HDMI_TX0P: J26.7 U24.1(IO1_IN) U24.10(IO1_OUT) ; also on sheet 12
HDMI_TX1N: J26.6 U23.5(IO4_IN) U23.6(IO4_OUT) ; also on sheet 12
HDMI_TX1P: J26.4 U23.4(IO3_IN) U23.7(IO3_OUT) ; also on sheet 12
HDMI_TX2N: J26.3 U23.2(IO2_IN) U23.9(IO2_OUT) ; also on sheet 12
HDMI_TX2P: J26.1 U23.1(IO1_IN) U23.10(IO1_OUT) ; also on sheet 12
HDMI_TX_CEC: J26.13 R268.2(B) U4.3(I/O2) ; also on sheet 12
HDMI_TX_HOTPLUG: C149.1(A) J26.19 R8.2(B) U4.4(I/O3) ; also on sheet 12
HDMI_TX_SCL: J26.15 R186.1(A) U4.1(I/O1) ; also on sheet 12
HDMI_TX_SDA: J26.16 R187.1(A) U4.6(I/O4) ; also on sheet 12
HDMI_TXCN: J26.12 U24.5(IO4_IN) U24.6(IO4_OUT) ; also on sheet 12
HDMI_TXCP: J26.10 U24.4(IO3_IN) U24.7(IO3_OUT) ; also on sheet 12
IR_IN: D3.1(OUT) R140.1(A) ; also on sheet 12
LED0_BASE: R26.2(B) R67.2(B) ; also on sheet 13
LED0_LINK_ACT: R30.2(B) R79.2(B) ; also on sheet 13
LED_CTRL: R3.1(A) R31.2(B) R51.1(A) ; also on sheet 12
LED_GREEN: LED1.3(A2) Q2.3(C) R34.2(B)
LED_RED: LED1.1(A1) Q1.3(C) R2.2(B) R22.1(A)
NF_ALE_EMMC_PWREN: U19.17(ALE) ; also on sheet 13
NF_CLE: U19.16(CLE) ; also on sheet 13
NF_CSN0_EMMC_CMD: R212.2(B) U19.9(~{CE}) U22.W5(CMD) ; also on sheet 13
NF_DQ0_EMMC_D0: R189.2(B) U19.29(I/O0) U22.H3(DAT0) ; also on sheet 13
NF_DQ1_EMMC_D1: R12.2(B) U19.30(I/O1) U22.H4(DAT1) ; also on sheet 13
NF_DQ2_EMMC_D2: R29.2(B) U19.31(I/O2) U22.H5(DAT2) ; also on sheet 13
NF_DQ3_EMMC_D3: R58.2(B) U19.32(I/O3) U22.J2(DAT3) ; also on sheet 13
NF_DQ4_EMMC_D4: R176.2(B) U19.41(I/O4) U22.J3(DAT4) ; also on sheet 13
NF_DQ5_EMMC_D5: R177.2(B) U19.42(I/O5) U22.J4(DAT5) ; also on sheet 13
NF_DQ6_EMMC_D6: R188.2(B) U19.43(I/O6) U22.J5(DAT6) ; also on sheet 13
NF_DQ7_EMMC_D7_BOOT_SEL0: R202.2(B) U19.44(I/O7) U22.J6(DAT7) ; also on sheet 13
NF_RDY0_EMMC_RST: C115.1(A) R203.2(B) U19.7(R/B~) U22.U5(RSTN) ; also on sheet 13
NF_REN_EMMC_CLK: U19.8(~{RE}) U22.W6(CLK) ; also on sheet 13
NF_WEN_EMMC_DET: U19.18(~{WE}) ; also on sheet 13
NF_WP: R89.1(A) R215.2(B) U19.19(~{WP})
RF0: C135.1(A) L1.2(B) U7.3(RF0)
RF1: C50.1(A) L7.2(B) U2.7(RF) U7.2(RF1)
RFF0: C61.1(A) J5.1 L1.1(A)
RFF1: C60.1(A) J4.1 L7.1(A)
RX+_PHY0: R63.1(A) U8.3(IO2_P1) U8.6(IO2_P2) ; also on sheet 13
RX-_PHY0: R64.1(A) U8.4(IO2_N1) U8.5(IO2_N2) ; also on sheet 13
SDIO0_CARD_DETECT: J21.9(SWITCH_TERM) R155.2(B) ; also on sheet 13
SDIO0_CCLK_OUT: J21.5(CLK) ; also on sheet 13
SDIO0_CCMD: J21.3(CMD) R153.2(B) ; also on sheet 13
SDIO0_CDATA0: J21.7(DAT0) R152.2(B) ; also on sheet 13
SDIO0_CDATA1: J21.8(DAT1) R151.2(B) ; also on sheet 13
SDIO0_CDATA2: J21.1(DATA2) R156.2(B) ; also on sheet 13
SDIO0_CDATA3: J21.2(CD/DAT3) R154.2(B) ; also on sheet 13
SDIO0_PWREN: R76.1(A) R149.1(A) ; also on sheet 13
SDIO_3318: R151.1(A) R152.1(A) R153.1(A) R154.1(A) R156.1(A) ; also on sheet 13
TX+_PHY0: R61.1(A) U8.1(IO1_P1) U8.8(IO1_P2) ; also on sheet 13
TX-_PHY0: R62.1(A) U8.2(IO1_N1) U8.7(IO1_N2) ; also on sheet 13
UART0_RXD: J18.2 R136.2(B) ; also on sheet 12
UART0_TXD: J18.3 R135.2(B) ; also on sheet 12
USB0_DM: C141.1(A) D6.1(A) J12.2 ; also on sheet 13
USB0_DP: C139.1(A) D1.1(A) J12.3 ; also on sheet 13
USB1_DM: J2.4(D-) U2.4(DM) U7.7(DM) ; also on sheet 13
USB1_DP: J2.3(D+) U2.2(DP) U7.6(DP) ; also on sheet 13
USB2_DM: J13.2 ; also on sheet 12
USB2_DP: J13.3 ; also on sheet 12
N3764759: D19.1(K) R268.1(A)
N3772068: R64.2(B) T2.8(RD-)
N3772072: R63.2(B) T2.6(RD+)
N3772076: R62.2(B) T2.3(TD-)
N3772080: R61.2(B) T2.1(TD+)
N3772116: C153.1(A) C307.1(A) T2.2(CTD)
N3772132: J25.4 J25.5 R272.2(B)
N3772148: J25.2 T2.14(TX-)
N3772160: J25.1 T2.16(TX+)
N3772172: C23.1(A) R269.1(A) R270.1(A) R271.1(A) R272.1(A)
N3772208: J25.3 T2.11(RX+)
N3772220: J25.6 T2.9(RX-)
N3772224: R269.2(B) T2.10(CRX)
N3772232: R271.2(B) T2.15(CTX)
N3772240: J25.7 J25.8 R270.2(B)
N3772256: J25.11 R79.1(A)
N3772260: J25.9 R67.1(A)
N3772264: C154.1(A) C297.1(A) T2.7(CRD)
N3781008: C363.1(A) R66.1(A) U5.5(EN)
N3781036: R49.2(B) R57.1(A) R91.2(B)
N3781056: C54.1(A) R20.1(A) R72.1(A) R145.1(A) U5.12(OUTL)
N3781130: C32.2(B) U5.8(CP)
N3781142: C32.1(A) U5.7(CN)
N3781154: C33.2(B) U5.6(PVSS)
N3781158: C55.2(B) R19.2(B) R74.2(B) R146.1(A) U5.3(OUTR)
N3781204: C317.1(A) R19.1(A) R27.1(A) R193.2(B)
N3781238: C55.1(A) R27.2(B) U5.2(-INR)
N3781254: C351.2(B) R193.1(A)
N3781282: C54.2(B) R28.1(A) U5.13(-INL)
N3781298: C316.1(A) R20.2(B) R28.2(B) R194.1(A)
N3781318: C350.1(A) R194.2(B)
N3781322: R49.1(A) U5.11(UVP)
N3790654: C131.2(B) Q15.1(G) R77.2(B) R267.1(A)
N3790702: Q5.3(C) R267.2(B)
N3790706: Q5.1(B) R76.2(B)
N3790734: C47.1(A) C177.1(A) D3.3(VCC) R178.1(A)
N3790948: Q1.1(B) R3.2(B)
N3790952: Q2.1(B) R22.2(B)
N3798043: R15.1(A) U10.3(EN)
N3799055: C38.1(A) C118.1(A) J13.1 LB3.1 U12.5(OUT)
N3799249: R48.2(B) U10.4(ILIM)
N3799257: R11.1(A) U12.3(EN)
N3799311: C29.1(A) C122.1(A) J12.1 LB2.1 U10.5(OUT)
N3799665: R47.2(B) U12.4(ILIM)
N3811192: C123.1(A) C124.1(A) U22.K2(VDDI)
N3811208: R68.1(A) U19.39(NC24)
N3811268: R80.2(B) U19.38(NC23/VDDQ2)
N3829333: R71.2(B) U6.L8(ZQ)

Not connected (* = marked no-connect by the designer): J2 1(NC1) 6(NC2) 8(RF0) 11(RF1); J25 13(M1) 14(M2); J26 14 24(M1) 25(M2); J34 6(NC) 7(M1) 8(M2); U2 3(VDD+); U6 J1(NC1) J9(NC2) L1(NC3) L9(NC4); U7 4(XI) 9(SUSPEND) 10(WO_WLAN); U19 3(NC3) 4(NC4) 5(NC5) 6(NC6) 10(NC7) 11(NC8) 14(NC9) 15(NC10) 20(NC11) 21(NC12) 22(NC13) 26(NC17) 27(NC18) 28(NC19) 33(NC20) 35(NC22) 40(NC25) 45(NC26) 46(NC27) 47(NC28); U22 A4(NC_1) A6(NC_2) A9(NC_3) A11(NC_4) AA1(NC_122) AA2(NC_123) AA7(NC_124) AA8(NC_125) AA9(NC_126) AA10(NC_127) AA11(NC_128) AA12(NC_129) AA13(NC_130) AA14(NC_131) AE1(NC_132) AE14(NC_133) AG2(NC_134) AG13(NC_135) AH4(NC_136) AH6(NC_137) AH9(NC_138) AH11(NC_95) B2(NC_5) B13(NC_6) D1(NC_7) D14(NC_8) H1(NC_9) H2(NC_10) H6(NC_11) H7(NC_12) H8(NC_13) H9(NC_14) H10(NC_15) H11(NC_16) H12(NC_17) H13(NC_18) H14(NC_19) J1(NC_20) J7(NC_21) J8(NC_22) J9(NC_23) J10(NC_24) J11(NC_25) J12(NC_26) J13(NC_27) J14(NC_28) K1(NC_29) K3(NC_30) K5(NC_31) K7(NC_32) K8(NC_33) K9(NC_34) K10(NC_35) K11(NC_36) K12(NC_37) K13(NC_38) K14(NC_39) L1(NC_40) L2(NC_41) L3(NC_42) L4(A1) L12(NC_43) L13(NC_44) L14(NC_45) M1(NC_46) M2(NC_47) M3(NC_48) M5(NC_49) M8(NC_50) M9(NC_51) M10(NC_52) M12(NC_53) M13(NC_54) M14(NC_55) N1(NC_56) N2(NC_57) N3(NC_58) N10(NC_59) N12(NC_60) N13(NC_61) N14(NC_62) P1(NC_63) P2(NC_64) P3(NC_65) P10(NC_66) P12(NC_67) P13(NC_68) P14(NC_69) R1(NC_70) R2(NC_71) R3(NC_72) R5(NC_73) R12(NC_74) R13(NC_75) R14(NC_76) T1(NC_77) T2(NC_78) T3(NC_79) T5(NC_80) T12(NC_81) T13(NC_82) T14(NC_83) U1(NC_84) U2(NC_85) U3(NC_86) U6(NC_87) U7(NC_88) U10(NC_89) U12(NC_90) U13(NC_91) U14(NC_92) V1(NC_93) V2(NC_94) V3(NC_96) V12(NC_97) V13(NC_98) V14(NC_99) W1(NC_100) W2(NC_101) W3(NC_102) W7(NC_103) W8(NC_104) W9(NC_105) W10(NC_106) W11(NC_107) W12(NC_108) W13(NC_109) W14(NC_110) Y1(NC_111) Y3(NC_112) Y6(NC_113) Y7(NC_114) Y8(NC_115) Y9(NC_116) Y10(NC_117) Y11(NC_118) Y12(NC_119) Y13(NC_120) Y14(NC_121)

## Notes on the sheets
sheet 1
- HDMI TX
- ** HDMI Design guideline **
- A.routing
- The type and specification of the components  refer to the BOM
- 1.Route as 100 Ohm differential impedance.
- 2.Differential pairs should be routed on TOP layer only.
- 3.Differential pairs should be separated from other traces by GND .
- NA
- 2013-07-04
- ECA NO
- DATE
- B.trace length
- 1.The length for the differential pairs should be less than 5 inches.
- DESIGNED
- TIANSHOU 00171014
- 00001234
- 2.Match trace length of differential pairs, 5 mils max within a pair.
- HI3798MDMO1G_VERA
- C.component selection
- REVIEWED
- CHENYUZHU 00149603
- 1.REXT resistor should be 6.6K Ohm +/-1%.
- VER
- PART_NUMBER
- SHEET
- 18
- OF
- 18
- 2.ESD components are suggested for ports protection.
- A
- 03030001
- HUAWEI TECH CO.,LTD.
- 3.All equivalent capacitance of ESD components should be < 0.8pF.
sheet 2
- VDAC OUTPUT
- The type and specification of the components  refer to the BOM
- NA
- 2013-07-04
- ECA NO
- DATE
- TIANSHOU 00171014
- DESIGNED
- HI3798MDMO1G_VERA
- 00001234
- ** Design guideline **
- REVIEWED
- CHENYUZHU 00149603
- VER
- PART_NUMBER
- SHEET
- 17
- OF
- 18
- 1.All channel traces should be separated from other traces by GND.
- 2.ESD components are suggested for ports protection, default BAV99.
- A
- 03030001
- HUAWEI TECH CO.,LTD.
sheet 3
- FE PHY/UART
- Put C153 and C154 close to T2
- UART
- The type and specification of the components  refer to the BOM
- NA
- 2013-07-04
- ECA NO
- DATE
- DESIGNED
- TIANSHOU 00171014
- HI3798MDMO1G_VERA
- 00001234
- REVIEWED
- CHENYUZHU 00149603
- VER
- PART_NUMBER
- SHEET
- 16
- OF
- 18
- A
- 03030001
- HUAWEI TECH CO.,LTD.
sheet 4
- Audio Output
- 1%
- 1%
- 1%
- 1%
- 1%
- The type and specification of the components  refer to the BOM
- NA
- 2013-07-04
- ECA NO
- DATE
- DESIGNED
- TIANSHOU 00171014
- HI3798MDMO1G_VERA
- 00001234
- REVIEWED
- CHENYUZHU 00149603
- VER
- PART_NUMBER
- SHEET
- 15
- OF
- 18
- A
- 03030001
- HUAWEI TECH CO.,LTD.
sheet 5
- SD CARD/IR
- IR
- LED
- R ON+G OFF->STBY
- R OFF+G ON->WORK
- R OFF+G OFF->NO POWER
- The type and specification of the components  refer to the BOM
- NA
- 2013-07-04
- ECA NO
- DATE
- DESIGNED
- TIANSHOU 00171014
- 00001234
- HI3798MDMO1G_VERA
- REVIEWED
- CHENYUZHU 00149603
- VER
- PART_NUMBER
- SHEET
- 14
- OF
- 18
- A
- 03030001
- HUAWEI TECH CO.,LTD.
sheet 6
- USB2.0/USB3.0/WIFI
- ETA6010:Current=1.3A
- USB0:usb_boot/adb
- For Board Antenna
- ANTF:50ohm Resistance
- For Board Antenna
- ANTF:50ohm Resistance
- ETA6010:Current=1.3A
- The type and specification of the components  refer to the BOM
- NA
- 2013-07-04
- ECA NO
- DATE
- TIANSHOU 00171014
- DESIGNED
- HI3798MDMO1G_VERA
- 00001234
- REVIEWED
- CHENYUZHU 00149603
- VER
- PART_NUMBER
- SHEET
- 13
- OF
- 18
- A
- 03030001
- HUAWEI TECH CO.,LTD.
sheet 7
- NAND FLASH/EMMC
- NAND FLASH
- eMMC/fSD
- fSD  10K
- NFWP
- 4GB
- H6 eMMC5.0
- 0:Protect
- fSD
- 1:NOT Protect
- 4GB
- NAND FLASH
- C142=C143=100nF,C36=1uF,R215=4.7K,R68=0,C88=100uF,D2=diode,U19=nand
- others=NC,If use Micron nand flash,R68=NC
- Pay attention to pin38&pin39,these pins are NC for the MLC NAND of some
- eMMC
- brands(such as Micron),but it should be connected to the VCC of
- others(such as Toshiba and Hynix).
- Pls refer to the corresponding datasheet for detail.
- C63=C123=C124=C93=C105=C323=C324=100nF,C275=2.2uF
- ,R203=R189=R12=R29=R58=R176=R177=R188=R202=47K,R212=10K,R94=0,U22=eMMC,others=NC
- T5 eMMC5.0
- fSD
- C63=C123=C124=C93=C105=C323=C324=100nF,C275=2.2uF
- ,R203=R189=R12=R29=R58=R212=10K,R94=0,U22=fSD,others=NC
- R5 eMMC5.0
- The type and specification of the components  refer to the BOM
- NA
- 2013-07-04
- ECA NO
- DATE
- DESIGNED
- TIANSHOU 00171014
- HI3798MDMO1G_VERA
- 00001234
- REVIEWED
- CHENYUZHU 00149603
- VER
- PART_NUMBER
- SHEET
- 12
- OF
- 18
- A
- 03030001
- HUAWEI TECH CO.,LTD.
sheet 8
- DDRB
- 1%
- 1%
- 1%
- 1%
- 1%
- 1%
- The type and specification of the components  refer to the BOM
- NA
- 2013-07-04
- ECA NO
- DATE
- DESIGNED
- TIANSHOU 00171014
- 00001234
- HI3798MDMO1G_VERA
- REVIEWED
- CHENYUZHU 00149603
- VER
- PART_NUMBER
- SHEET
- 11
- OF
- 18
- A
- 03030001
- HUAWEI TECH CO.,LTD.
